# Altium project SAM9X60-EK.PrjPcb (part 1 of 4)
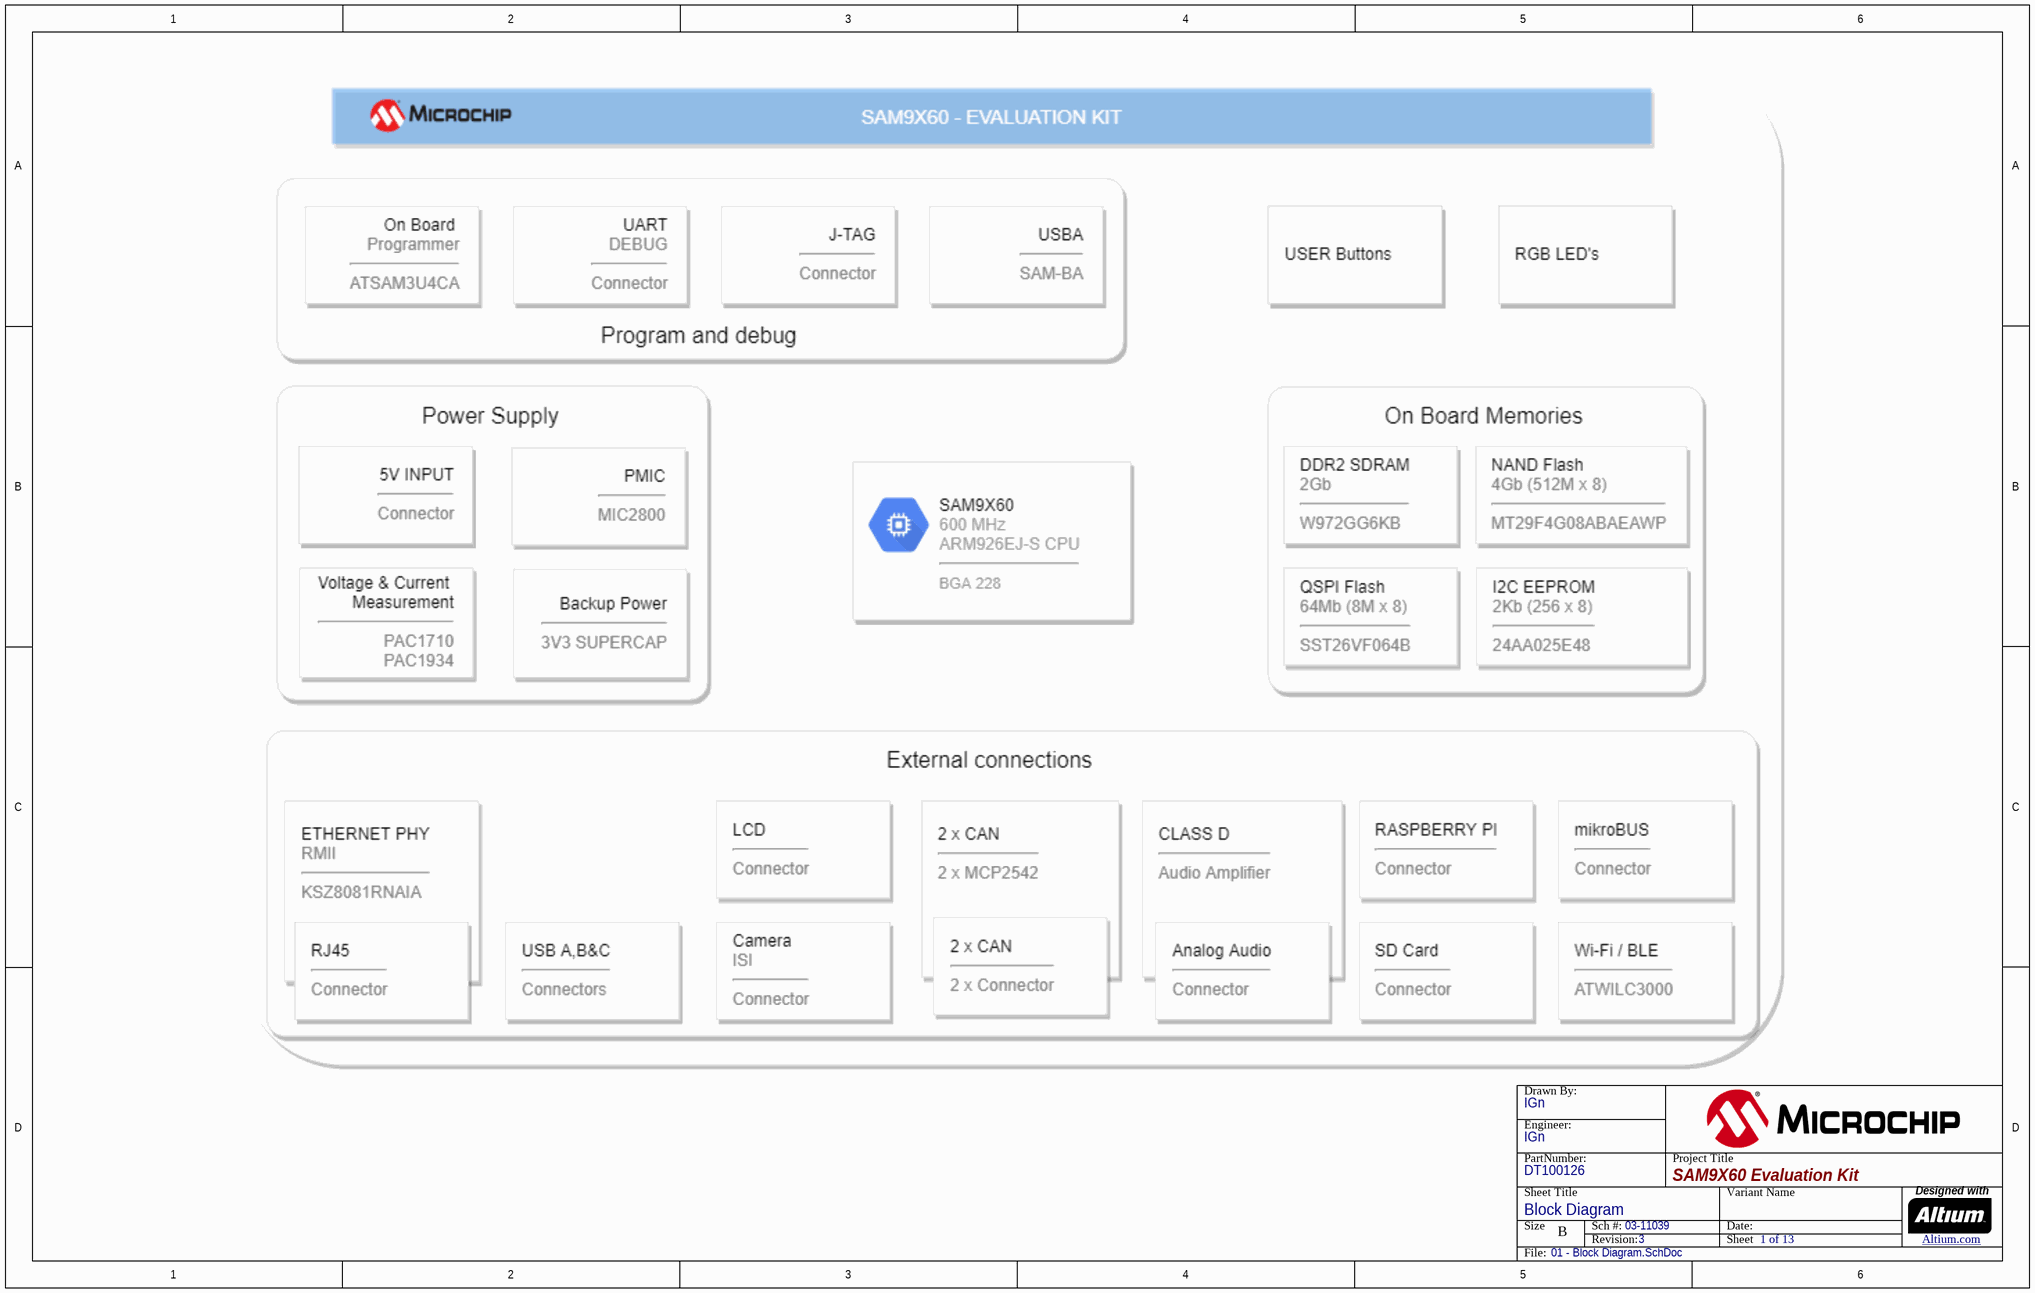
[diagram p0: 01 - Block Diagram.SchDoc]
ProjectBoardNumber: 11039; ProjectDrawnBy: IGn; ProjectEngineer: IGn; ProjectName: SAM9X60-EK; ProjectPartNumber: DT100126; ProjectRevisionART: 3; ProjectRevisionASSY: 3; ProjectRevisionFAB: 3; ProjectRevisionSCH: 3; ProjectTitle: SAM9X60 Evaluation Kit
13 sheets, 588 parts. Net scope: global (net labels, ports and power ports of the same name join across sheets).
Board file: SAM9X60-EK.PcbDoc
Sheets:
  01 - Block Diagram.SchDoc
  02 - Power supply.SchDoc
  03 - Processor SAM9X60.SchDoc
  04 - Processor IOs.SchDoc
  05 - Processor IO Expansions.SchDoc
  06 - On Board Memories.SchDoc
  07 - USB ports.SchDoc
  08 - Ethernet MAC.SchDoc
  09 - Wi-Fi BT module.SchDoc
  10 - SDMMC, CAN & CLASSD.SchDoc
  11 - Expansion connectors.SchDoc
  12 - User Interaction.SchDoc
  13 - On Board JLINK.SchDoc

## Sheet 01 - Block Diagram.SchDoc
size B; CompanyName: Microchip Technology Inc.; Organization: Microchip Technology; Address1: 2355 West Chandler Blvd.; Address2: Chandler, AZ  85224; Address4: USA; DocumentNumber: 1; SheetNumber: 1; SheetTotal: 13; SheetTitle: Block Diagram

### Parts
(Parts that share a designator on the sheet are numbered #1, #2 ... from top to bottom, then left to right.)
?#1  (no value)  (graphical)

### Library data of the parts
?#1 = Title Block B

## Sheet 02 - Power supply.SchDoc
size B; CompanyName: Microchip Technology Inc.; Organization: Microchip Technology; Address1: 2355 West Chandler Blvd.; Address2: Chandler, AZ  85224; Address4: USA; DocumentNumber: 2; SheetNumber: 2; SheetTotal: 13; SheetTitle: Power supply
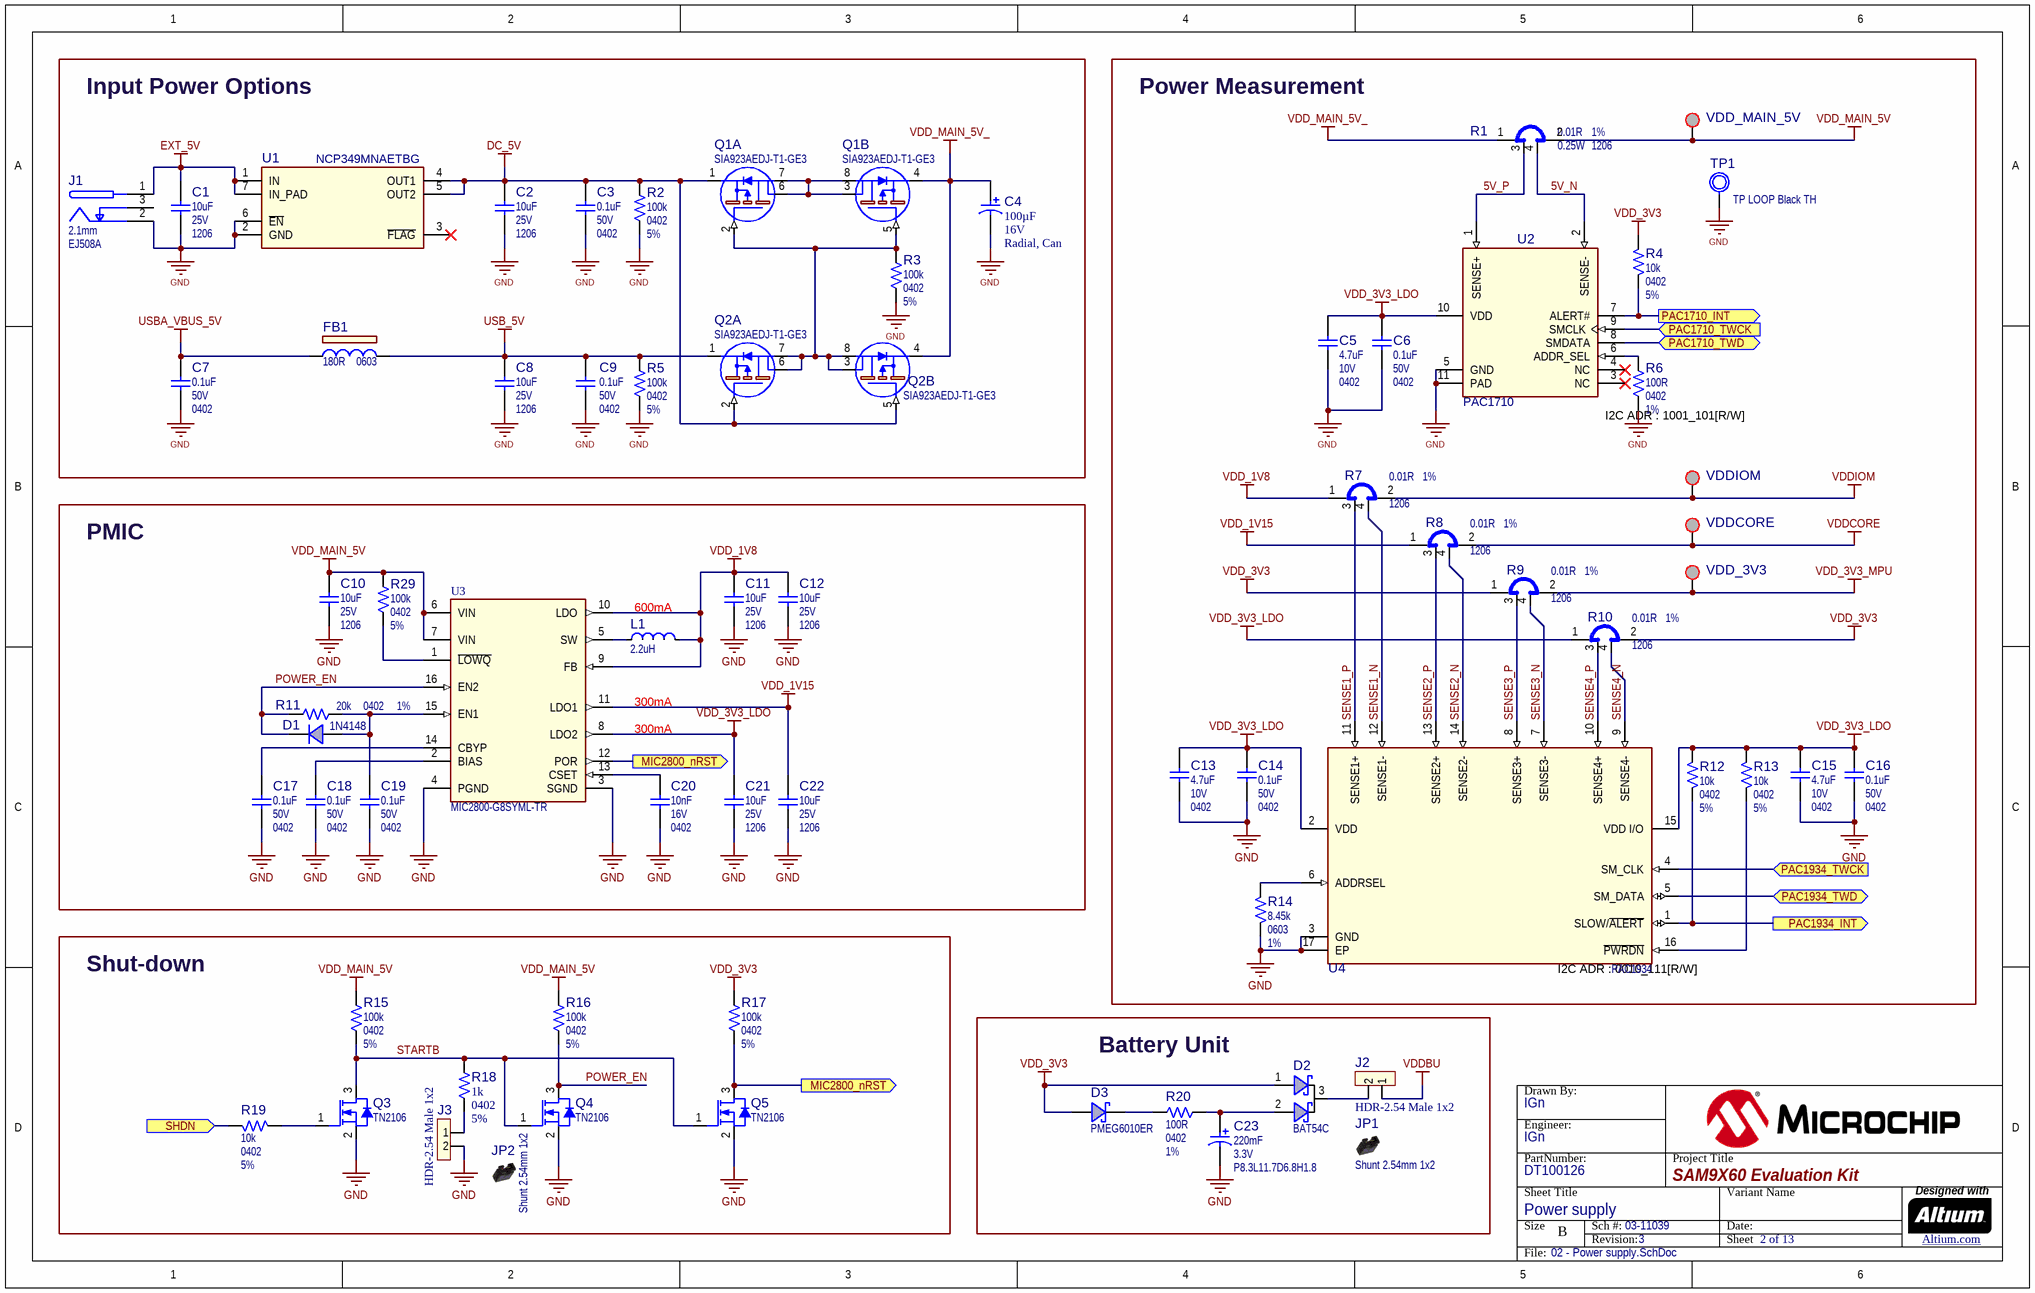
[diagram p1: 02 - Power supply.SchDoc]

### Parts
(Parts that share a designator on the sheet are numbered #1, #2 ... from top to bottom, then left to right.)
?#2  (no value)  (graphical)
C1  value 10uF  Voltage: 25V  Package: 1206  [CAP_C_1206]  (hidden comment: Capacitor NP)
C2  value 10uF  Voltage: 25V  Package: 1206  [CAP_C_1206]  (hidden comment: Capacitor NP)
C3  value 0.1uF  Voltage: 50V  Package: 0402  [CAP_C_0402]  (hidden comment: Capacitor NP)
C4  value 100µF  Voltage: 16V  Package: Radial, Can  [CAP_RAD_P2D5H12.5]  (hidden comment: Capacitor POL)
C5  value 4.7uF  Voltage: 10V  Package: 0402  [CAP_C_0402]  (hidden comment: Capacitor NP)
C6  value 0.1uF  Voltage: 50V  Package: 0402  [CAP_C_0402]  (hidden comment: Capacitor NP)
C7  value 0.1uF  Voltage: 50V  Package: 0402  [CAP_C_0402]  (hidden comment: Capacitor NP)
C8  value 10uF  Voltage: 25V  Package: 1206  [CAP_C_1206]  (hidden comment: Capacitor NP)
C9  value 0.1uF  Voltage: 50V  Package: 0402  [CAP_C_0402]  (hidden comment: Capacitor NP)
C10  value 10uF  Voltage: 25V  Package: 1206  [CAP_C_1206]  (hidden comment: Capacitor NP)
C11  value 10uF  Voltage: 25V  Package: 1206  [CAP_C_1206]  (hidden comment: Capacitor NP)
C12  value 10uF  Voltage: 25V  Package: 1206  [CAP_C_1206]  (hidden comment: Capacitor NP)
C13  value 4.7uF  Voltage: 10V  Package: 0402  [CAP_C_0402]  (hidden comment: Capacitor NP)
C14  value 0.1uF  Voltage: 50V  Package: 0402  [CAP_C_0402]  (hidden comment: Capacitor NP)
C15  value 4.7uF  Voltage: 10V  Package: 0402  [CAP_C_0402]  (hidden comment: Capacitor NP)
C16  value 0.1uF  Voltage: 50V  Package: 0402  [CAP_C_0402]  (hidden comment: Capacitor NP)
C17  value 0.1uF  Voltage: 50V  Package: 0402  [CAP_C_0402]  (hidden comment: Capacitor NP)
C18  value 0.1uF  Voltage: 50V  Package: 0402  [CAP_C_0402]  (hidden comment: Capacitor NP)
C19  value 0.1uF  Voltage: 50V  Package: 0402  [CAP_C_0402]  (hidden comment: Capacitor NP)
C20  value 10nF  Voltage: 16V  Package: 0402  [CAP_C_0402]  (hidden comment: Capacitor NP)
C21  value 10uF  Voltage: 25V  Package: 1206  [CAP_C_1206]  (hidden comment: Capacitor NP)
C22  value 10uF  Voltage: 25V  Package: 1206  [CAP_C_1206]  (hidden comment: Capacitor NP)
C23  value 220mF  Voltage: 3.3V  Package: P8.3L11.7D6.8H1.8  [CAP_AX_P8.3L11.7D6.8H1.8]  (hidden comment: Capacitor POL)
D1  value 1N4148  [SOD-323]  (hidden comment: Diode Single)
D2  value BAT54C  [SOT-23-3]  (hidden comment: Diode Schottky Dual CK)
D3  value PMEG6010ER  [SOD-123]  (hidden comment: Diode Schottky)
FB1  value 180R  Package: 0603  [IND_C_0603]  (hidden comment: Ferrite Bead)
J1  value 2.1mm  Manufacturer Part Number 1: EJ508A  [CON_JACK_POWER_TH_RA_MPD_EJ508A]  (hidden comment: CON JACK 2C 3P SPST)
J2  value HDR-2.54 Male 1x2  [HDR_M_2.54_1x2]  (hidden comment: Header 1x2)
J3  value HDR-2.54 Male 1x2  [HDR_M_2.54_1x2]  (hidden comment: Header 1x2)
JP1  value Shunt 2.54mm 1x2  [Jumper_Mechanical]  (hidden comment: Jumper Mechanical)  (mechanical)
JP2  value Shunt 2.54mm 1x2  [Jumper_Mechanical]  (hidden comment: Jumper Mechanical)  (mechanical)
L1  value 2.2uH  [IND_C_1008]  (hidden comment: Inductor)
Q1  SIA923AEDJ-T1-GE3  [SiA923AEDJ PPAK_SC70_6L]  (parts A,B of 2)
Q2  SIA923AEDJ-T1-GE3  [SiA923AEDJ PPAK_SC70_6L]  (parts A,B of 2)
Q3  value TN2106  [SOT-23-3]  (hidden comment: Transistor MOS-N GSD)
Q4  value TN2106  [SOT-23-3]  (hidden comment: Transistor MOS-N GSD)
Q5  value TN2106  [SOT-23-3]  (hidden comment: Transistor MOS-N GSD)
R1  value 0.01R  Package: 1206  Tolerance: 1%  Power: 0.25W  [RES_C_1206_SHUNT]  (hidden comment: Shunt 4 Pin)
R2  value 100k  Package: 0402  Tolerance: 5%  [RES_C_0402]  (hidden comment: Resistor)
R3  value 100k  Package: 0402  Tolerance: 5%  [RES_C_0402]  (hidden comment: Resistor)
R4  value 10k  Package: 0402  Tolerance: 5%  [RES_C_0402]  (hidden comment: Resistor)
R5  value 100k  Package: 0402  Tolerance: 5%  [RES_C_0402]  (hidden comment: Resistor)
R6  value 100R  Package: 0402  Tolerance: 1%  [RES_C_0402]  (hidden comment: Resistor)
R7  value 0.01R  Package: 1206  Tolerance: 1%  [RES_C_1206_SHUNT]  (hidden comment: Shunt 4 Pin)
R8  value 0.01R  Package: 1206  Tolerance: 1%  [RES_C_1206_SHUNT]  (hidden comment: Shunt 4 Pin)
R9  value 0.01R  Package: 1206  Tolerance: 1%  [RES_C_1206_SHUNT]  (hidden comment: Shunt 4 Pin)
R10  value 0.01R  Package: 1206  Tolerance: 1%  [RES_C_1206_SHUNT]  (hidden comment: Shunt 4 Pin)
R11  value 20k  Package: 0402  Tolerance: 1%  [RES_C_0402]  (hidden comment: Resistor)
R12  value 10k  Package: 0402  Tolerance: 5%  [RES_C_0402]  (hidden comment: Resistor)
R13  value 10k  Package: 0402  Tolerance: 5%  [RES_C_0402]  (hidden comment: Resistor)
R14  value 8.45k  Package: 0603  Tolerance: 1%  [RES_C_0603]  (hidden comment: Resistor)
R15  value 100k  Package: 0402  Tolerance: 5%  [RES_C_0402]  (hidden comment: Resistor)
R16  value 100k  Package: 0402  Tolerance: 5%  [RES_C_0402]  (hidden comment: Resistor)
R17  value 100k  Package: 0402  Tolerance: 5%  [RES_C_0402]  (hidden comment: Resistor)
R18  value 1k  Package: 0402  Tolerance: 5%  [RES_C_0402]  (hidden comment: Resistor)
R19  value 10k  Package: 0402  Tolerance: 5%  [RES_C_0402]  (hidden comment: Resistor)
R20  value 100R  Package: 0402  Tolerance: 1%  [RES_C_0402]  (hidden comment: Resistor)
R29  value 100k  Package: 0402  Tolerance: 5%  [RES_C_0402]  (hidden comment: Resistor)
TP1  value TP LOOP Black TH  [CON_TP_TH_V_BLK_KEC_5011]  (hidden comment: GND)
U1  value NCP349MNAETBG  [DFN-6_2x1.6_EP0.4x0.35]  (hidden comment: NCP349 DFN-6)
U2  value PAC1710  [DFN-10_3x3]  (hidden comment: PAC1710 DFN-10)
U3  value MIC2800-G8SYML-TR  [QFN-16_3X3]  (hidden comment: MIC2800 VFQFN-16)
U4  value PAC1934  [UQFN-16_4X4_EP2.6X2.6]  (hidden comment: PAC1934 UQFN-16)
VDD_3V3  SMD Test Point  [TP_1x1_SMD]  (value not drawn)  (no BOM)
VDD_MAIN_5V  SMD Test Point  [TP_1x1_SMD]  (value not drawn)  (no BOM)
VDDCORE  SMD Test Point  [TP_1x1_SMD]  (value not drawn)  (no BOM)
VDDIOM  SMD Test Point  [TP_1x1_SMD]  (value not drawn)  (no BOM)

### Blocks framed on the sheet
Input Power Options: C1-C4 C7-C9 FB1 J1 Q1 Q2 R2 R3 R5 U1
Power Measurement: C5 C6 C13-C16 R1 R4 R6-R10 R12-R14 TP1 U2 U4 VDD_3V3 VDD_MAIN_5V VDDCORE VDDIOM
PMIC: C10-C12 C17-C22 D1 L1 R11 R29 U3
Shut-down: J3 JP2 Q3-Q5 R15-R19
Battery Unit: C23 D2 D3 J2 JP1 R20

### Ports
MIC2800_nRST (out), PAC1710_INT (out), PAC1710_TWCK (in), PAC1710_TWD (bidir), PAC1934_INT (out), PAC1934_TWCK (in), PAC1934_TWD (bidir), SHDN (in)

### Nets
DC_5V: C2.1 C3.1 Q1.1(S1) Q2.2(G1) Q2.5(G2) R2.2 U1.4(OUT1) U1.5(OUT2)
EXT_5V: C1.1 J1.1(PLUS) U1.1(IN) U1.7(IN_PAD)
GND: C1.2 C2.2 C3.2 C4.2 C5.1 C6.1 C7.2 C8.2 C9.2 C10.2 C11.2 C12.2 C13.1 C14.1 C15.1 C16.1 C17.2 C18.2 C19.2 C20.2 C21.2 C22.2 C23.2 J1.2(COM) J3.2 Q3.2(S) Q4.2(S) Q5.2(S) R2.1 R3.1 R5.1 R6.2 R14.1 TP1.1 U1.2(GND) U1.6(~{EN}) U2.5(GND) U2.11(PAD) U3.3(SGND) U3.4(PGND) U4.3(GND) U4.17(EP)
USB_5V: C8.1 C9.1 FB1.2 Q2.1(S1) R5.2
USBA_VBUS_5V: C7.1 FB1.1
VDD_1V8: C11.1 C12.1 L1.2(F) R7.1 U3.9(FB) U3.10(LDO)
VDD_1V15: C22.1 R8.1 U3.11(LDO1)
VDD_3V3: D2.1(A) D3.1(A) R4.2 R9.1 R10.2 R17.2
VDD_3V3_LDO: C5.2 C6.2 C13.2 C14.2 C15.2 C16.2 C21.1 R10.1 R12.2 R13.2 U2.10(VDD) U3.8(LDO2) U4.2(VDD) U4.15(VDD_I/O)
VDD_3V3_MPU: R9.2 VDD_3V3.1
VDD_MAIN_5V: C10.1 R1.2 R15.2 R16.2 R29.2 U3.6(VIN) U3.7(VIN) VDD_MAIN_5V.1
VDD_MAIN_5V_: C4.1 Q1.4(S2) Q2.4(S2) R1.1
VDDBU: J2.1
VDDCORE: R8.2 VDDCORE.1
VDDIOM: R7.2 VDDIOM.1
5V_N: R1.4 U2.2(SENSE-)
5V_P: R1.3 U2.1(SENSE+)
MIC2800_nRST: Q5.3(D) R17.1 U3.12(POR) ; port MIC2800_nRST
PAC1710_INT: R4.1 U2.7(ALERT#) ; port PAC1710_INT
PAC1710_TWCK: U2.9(SMCLK) ; port PAC1710_TWCK
PAC1710_TWD: U2.8(SMDATA) ; port PAC1710_TWD
PAC1934_INT: R12.1 U4.1(SLOW/~{ALERT}) ; port PAC1934_INT
PAC1934_TWCK: U4.4(SM_CLK) ; port PAC1934_TWCK
PAC1934_TWD: U4.5(SM_DATA) ; port PAC1934_TWD
POWER_EN: D1.2(K) Q4.3(D) R11.1 R16.1 U3.16(EN2)
SENSE1_N: R7.4 U4.12(SENSE1-)
SENSE1_P: R7.3 U4.11(SENSE1+)
SENSE2_N: R8.4 U4.14(SENSE2-)
SENSE2_P: R8.3 U4.13(SENSE2+)
SENSE3_N: R9.4 U4.7(SENSE3-)
SENSE3_P: R9.3 U4.8(SENSE3+)
SENSE4_N: R10.4 U4.9(SENSE4-)
SENSE4_P: R10.3 U4.10(SENSE4+)
SHDN: R19.2 ; port SHDN
STARTB: Q3.3(D) Q4.1(G) Q5.1(G) R15.1 R18.2
NetC17_1: C17.1 U3.14(CBYP)
NetC18_1: C18.1 U3.2(BIAS)
NetC19_1: C19.1 D1.1(A) R11.2 U3.15(EN1)
NetC20_1: C20.1 U3.13(CSET)
NetC23_1: C23.1 D2.2(A) R20.2
NetD2_3: D2.3(KK) J2.2
NetD3_2: D3.2(K) R20.1
NetJ3_1: J3.1 R18.1
NetL1_1: L1.1(S) U3.5(SW)
NetQ1_2: Q1.2(G1) Q1.5(G2) Q2.3(D2) Q2.6(D1) Q2.7(D1_2) Q2.8(D2_2) R3.2
NetQ1_3: Q1.3(D2) Q1.6(D1) Q1.7(D1_2) Q1.8(D2_2)
NetQ3_1: Q3.1(G) R19.1
NetR6_1: R6.1 U2.6(ADDR_SEL)
NetR13_1: R13.1 U4.16(~{PWRDN})
NetR14_2: R14.2 U4.6(ADDRSEL)
NetR29_1: R29.1 U3.1(~{LOWQ})

Not connected (* = marked no-connect by the designer): J1 3(SWITCH); U1 3(~{FLAG})*; U2 3(NC)* 4(NC)*

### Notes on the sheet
- I2C ADR : 1001_101[R/W]
- (near L1) 600mA
- 300mA
- (near U4) I2C ADR : 0010_111[R/W]

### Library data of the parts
?#2 = Title Block B
C1 C2 C8 C10-C12 C21 C22 = CAP1418: Capacitor; Manufacturer 1: Samsung Electro-Mechanics America, Inc; Manufacturer Part Number 1: CL31B106KAHNFNE; Description_: CAP CER 10uF 25V 10% X7R SMD 1206; Dev Tools Status: Design; Tolerance: 10%; Temperature Coeffcient: X7R; Type: Ceramic; Populated: YES; Owner: Sorin Stanoaia
C3 C6 C7 C9 C14 C16-C19 = CAP1463: Capacitor; Manufacturer 1: TDK Corporation; Manufacturer Part Number 1: C1005X7R1H104K050BB; Description_: CAP CER 0.1uF 50V 10% X7R SMD 0402; Dev Tools Status: Production; Tolerance: 10%; Temperature Coeffcient: X7R; Type: Ceramic; Owner: Jamus Griego; Populated: YES
C4 = CAP1834: Capacitor; Manufacturer 1: Wurth Electronics Inc.; Manufacturer Part Number 1: 860010372006; Description_: CAP 100 UF 20% 16 V; Dev Tools Status: Design; Tolerance: ±20%; Type: Aluminum; Owner: Ed Kennedy; Populated: YES
C5 C13 C15 = CAP1684: Capacitor; Manufacturer 1: TDK Corporation; Manufacturer Part Number 1: C1005X5R1A475K050BC; Description_: CAP CER 4.7uF 10V 10% X5R SMD 0402; Dev Tools Status: Production; Tolerance: 10%; Temperature Coeffcient: X5R; Type: Ceramic; Owner: Jesus Aviles; Populated: YES
C20 = CAP0278: Capacitor; Manufacturer 1: KEMET; Manufacturer Part Number 1: C0402C103K4RACTU; Description_: CAP CER 10000pF 16V 10% X7R SMD 0402; Dev Tools Status: Production; Tolerance: 10%; Temperature Coeffcient: X7R; Type: Ceramic; Populated: YES
C23 = CAP1762: Capacitor; Manufacturer 1: Elna America; Manufacturer Part Number 1: DSK-3R3H204T614-H2L; Description_: CAP SUPERCAP 200mF 3.3V -20% +80% 200Ohm AX P8.3L11.7D6.8H1.8; Dev Tools Status: Production; Tolerance: -20%, +80%; ESR: 200R; Type: Supercap; Owner: Alexandru Chiser - M19201; Populated: YES
D1 = DIODE0096: Manufacturer 1: Diodes Incorporated; Manufacturer Part Number 1: 1N4148WS-7-F; Description_: DIO RECT 1N4148WS 1.25V 150mA 75V SOD-323; Dev Tools Status: Production; Type: Rectifier Single; Forward Current: 150mA; Power: 200mW; Reverse Current: 50uA; Reverse Voltage: 75V; Populated: YES
D2 = DIODE0056: Manufacturer 1: Diodes Incorporated; Manufacturer Part Number 1: BAT54CTA; Description_: DIO SCTKYARR BAT54C 530mV 200mA 30V SOT-23-3; Dev Tools Status: Production; Type: Schottky Array; Forward Current: 200mA; Power: 330mW; Reverse Current: 2.5uA; Reverse Voltage: 30V; Populated: Yes
D3 = DIODE1254: DIO SCTKY RB160M-60TR 550mV 1A 60V SMD SOD-123F; Manufacturer 1: NXP Semiconductors                                                                               NXP Semiconductors; Manufacturer Part Number 1: PMEG6010ER,115; Description_: DIODE SCTKY PMEG6010ER 530mV 1A 60V SMD SOD-123; Dev Tools Status: Design; Type: Schottky Single; Power: 0.95W; Reverse Current: 60uA; Reverse Recovery Time: 500ns; Owner: Sorin Stanoaia; Populated: YES
FB1 = IND1453: Manufacturer 1: Murata Electronics North America; Manufacturer Part Number 1: BLM18PG181SN1D; Description_: FERRITE 180R 1.5A SMD 0603; Dev Tools Status: Design; Owner: Dragos Danaila; DCR: 0.09R; Saturation Current: 1.5A; Test Frequency: 100MHz; Populated: YES
J1 = CON1560: Manufacturer 1: MPD (Memory Protection Devices); Description_: CON POWER 2.1mm 5.5mm Switch Slotted TH R/A; Dev Tools Status: Production; Owner: Mark Loper; Populated: YES
J2 J3 = CON1312: Manufacturer 1: Sullins Connector Solutions; Manufacturer Part Number 1: PREC002SAAN-RC; Description_: CON HDR-2.54 Male 1x2 Tin 5.84MH TH VERT; Dev Tools Status: Production; Owner: Randolph Sobrepena; Populated: YES
JP1 JP2 = HW1006: Manufacturer 1: 3M; Manufacturer Part Number 1: 969102-0000-DA; MCHP-ID: HW1006; Description_: MECH HW JUMPER 2.54mm 1x2; Dev Tools Status: Production; Owner: Mike Ragsdale; Populated: MECH
L1 = IND1348: Manufacturer 1: TDK; Manufacturer Part Number 1: MLP2520H2R2MT0S1; Description_: INDUCTOR 2.2uH 1.3A 20% SMD 1008; Dev Tools Status: Design; Owner: Razvan Cristescu; DCR: 0.117R; RMS Current: 1.3A; Test Frequency: 2MHz; Populated: YES
Q1 Q2 = TRA1245: Manufacturer 1: Vishay Siliconix; Description_: TRANS FET DUAL P+P SIA923AEDJ -20V -4.5A 7.8W SC70-6L; Dev Tools Status: Design; Type: FET; Current: -4.5A; Drain to Source Voltage: -20V; Gate to Source Voltage: 900mV; Power: 7.8W; Owner: Dragos Danaila; Populated: YES
Q3-Q5 = MIC7420: Transistor MOS; Manufacturer 1: Microchip Technology; Manufacturer Part Number 1: TN2106K1-G; Description_: MCHP ANALOG MOSFET N-CH TN2106 60V 280mA 360mW 2.5R SOT23-3; Type: MOSFET; Dev Tools Status: Production; Owner: Ilie Galan; Populated: YES
R1 = RSMT1231: Shunt; Manufacturer 1: Yageo; Manufacturer Part Number 1: PF1206FRF070R01L; Description_: RES SHUNT 0.01R 1% 1/4W 1206; Dev Tools Status: Design; Voltage: 50mV; Temperature Coeffcient: 100ppm/C; Current: 5A; Owner: Dragos Danaila; Populated: YES
R2 R3 R5 R15-R17 R29 = RES2196: Manufacturer 1: Yageo; Manufacturer Part Number 1: RC0402JR-07100KL; Description_: RES TKF 100k 5% 1/16W SMD 0402; Dev Tools Status: Design; Temperature Coeffcient: 100ppm/C; Power: 1/16W; Owner: Ilie Galan; Populated: YES
R4 R12 R13 R19 = RSMT0439: Manufacturer 1: Vishay; Manufacturer Part Number 1: CRCW040210K0JNED; Description_: RES TKF 10k 5% 1/16W SMD 0402; Dev Tools Status: Production; Voltage: 50V; Temperature Coeffcient: 100ppm/C; Power: 1/16W; Populated: Yes
R6 R20 = RES1587: Manufacturer 1: Yageo; Manufacturer Part Number 1: RC0402FR-07100RL; Description_: RES TKF 100R 1% 1/16W SMD 0402; Dev Tools Status: Design; Voltage: 50V; Temperature Coeffcient: 100ppm/C; Power: 1/16W; Owner: Sorin Stanoaia; Populated: YES
R7-R10 = RSMT1231: Shunt; Manufacturer 1: Yageo; Manufacturer Part Number 1: PF1206FRF070R01L; Description_: RES SHUNT 0.01R 1% 1/4W 1206; Dev Tools Status: Design; Voltage: 50mV; Temperature Coeffcient: 100ppm/C; Current: 5A; Power: 1/4W; Owner: Dragos Danaila; Populated: YES
R11 = RSMT1238: Manufacturer 1: Yageo; Manufacturer Part Number 1: RC0402FR-0720KL; Description_: RES TKF 20K 1% 1/16W SMD 0402; Dev Tools Status: Design; Voltage: 100V; Temperature Coeffcient: 100ppm/C; Current: 1A; Power: 1/16; Owner: Dragos Danaila; Populated: YES
R14 = RSMT0440: Manufacturer 1: Yageo; Manufacturer Part Number 1: 9C06031A8451FKHFT; Description_: RES TKF 8.45k 1% 1/10W SMD 0603; Dev Tools Status: Production; Voltage: 50V; Temperature Coeffcient: 100ppm/C; Power: 1/10W; Populated: Yes
R18 = RSMT0316: Manufacturer 1: Panasonic; Manufacturer Part Number 1: ERJ-2GEJ102X; Description_: RES TKF 1k 5% 1/16W SMD 0402; Dev Tools Status: Production; Voltage: 50V; Temperature Coeffcient: 200ppm/C; Power: 1/16W; Owner: Tad Ahlvers; Populated: YES
TP1 = MISC0025: Test Point; Manufacturer 1: Keystone; Manufacturer Part Number 1: 5011; Description_: CON TP LOOP Black TH; Dev Tools Status: Production; Owner: Tad Ahlvers; Populated: YES
U1 = IC1481: Manufacturer 1: ON Semiconductor; MCHP-ID: IC1481; Description_: IC POWER NCP349MNAETBG Power Supply Controller Overvoltage Protection DFN-6; Dev Tools Status: Design; Vin: 1.2 V to 28 V; Owner: Ciprian Abramov; Populated: YES
U2 = MIC6142: Manufacturer 1: Microchip Technology; Manufacturer Part Number 1: PAC1710-1-AIA-TR; Description_: MCHP ANALOG CURRENT SENSE MONITOR PAC1710-1-AIA-TR DFN-10; Dev Tools Status: Production; Owner: Bogdan Popescu; Populated: YES
U3 = MIC7858: Manufacturer 1: Microchip Technology; Manufacturer Part Number 1: MIC2800-G8SYML; Description_: MCHP ANALOG SWITCHER Buck 1.8V to 3.3V MIC2800-G8SYML-TR VFQFN-16; Dev Tools Status: Design; Owner: Dragos Danaila; Populated: YES
U4 = MIC7010: Manufacturer 1: Microchip Technology; Manufacturer Part Number 1: PAC1934-I/JQ; Description_: MCHP ANALOG POWER CURRENT SENSE MONITOR PAC1934-I/JQ UQFN-16; Dev Tools Status: Production; Owner: Razvan Cristescu; Populated: YES
VDD_3V3 VDD_MAIN_5V VDDCORE VDDIOM = TEST-POINT: Test Point pad 1.00mm

## Sheet 03 - Processor SAM9X60.SchDoc
size B; CompanyName: Microchip Technology Inc.; Organization: Microchip Technology; Address1: 2355 West Chandler Blvd.; Address2: Chandler, AZ  85224; Address4: USA; DocumentNumber: 3; SheetNumber: 3; SheetTotal: 13; SheetTitle: Processor SAM9X60
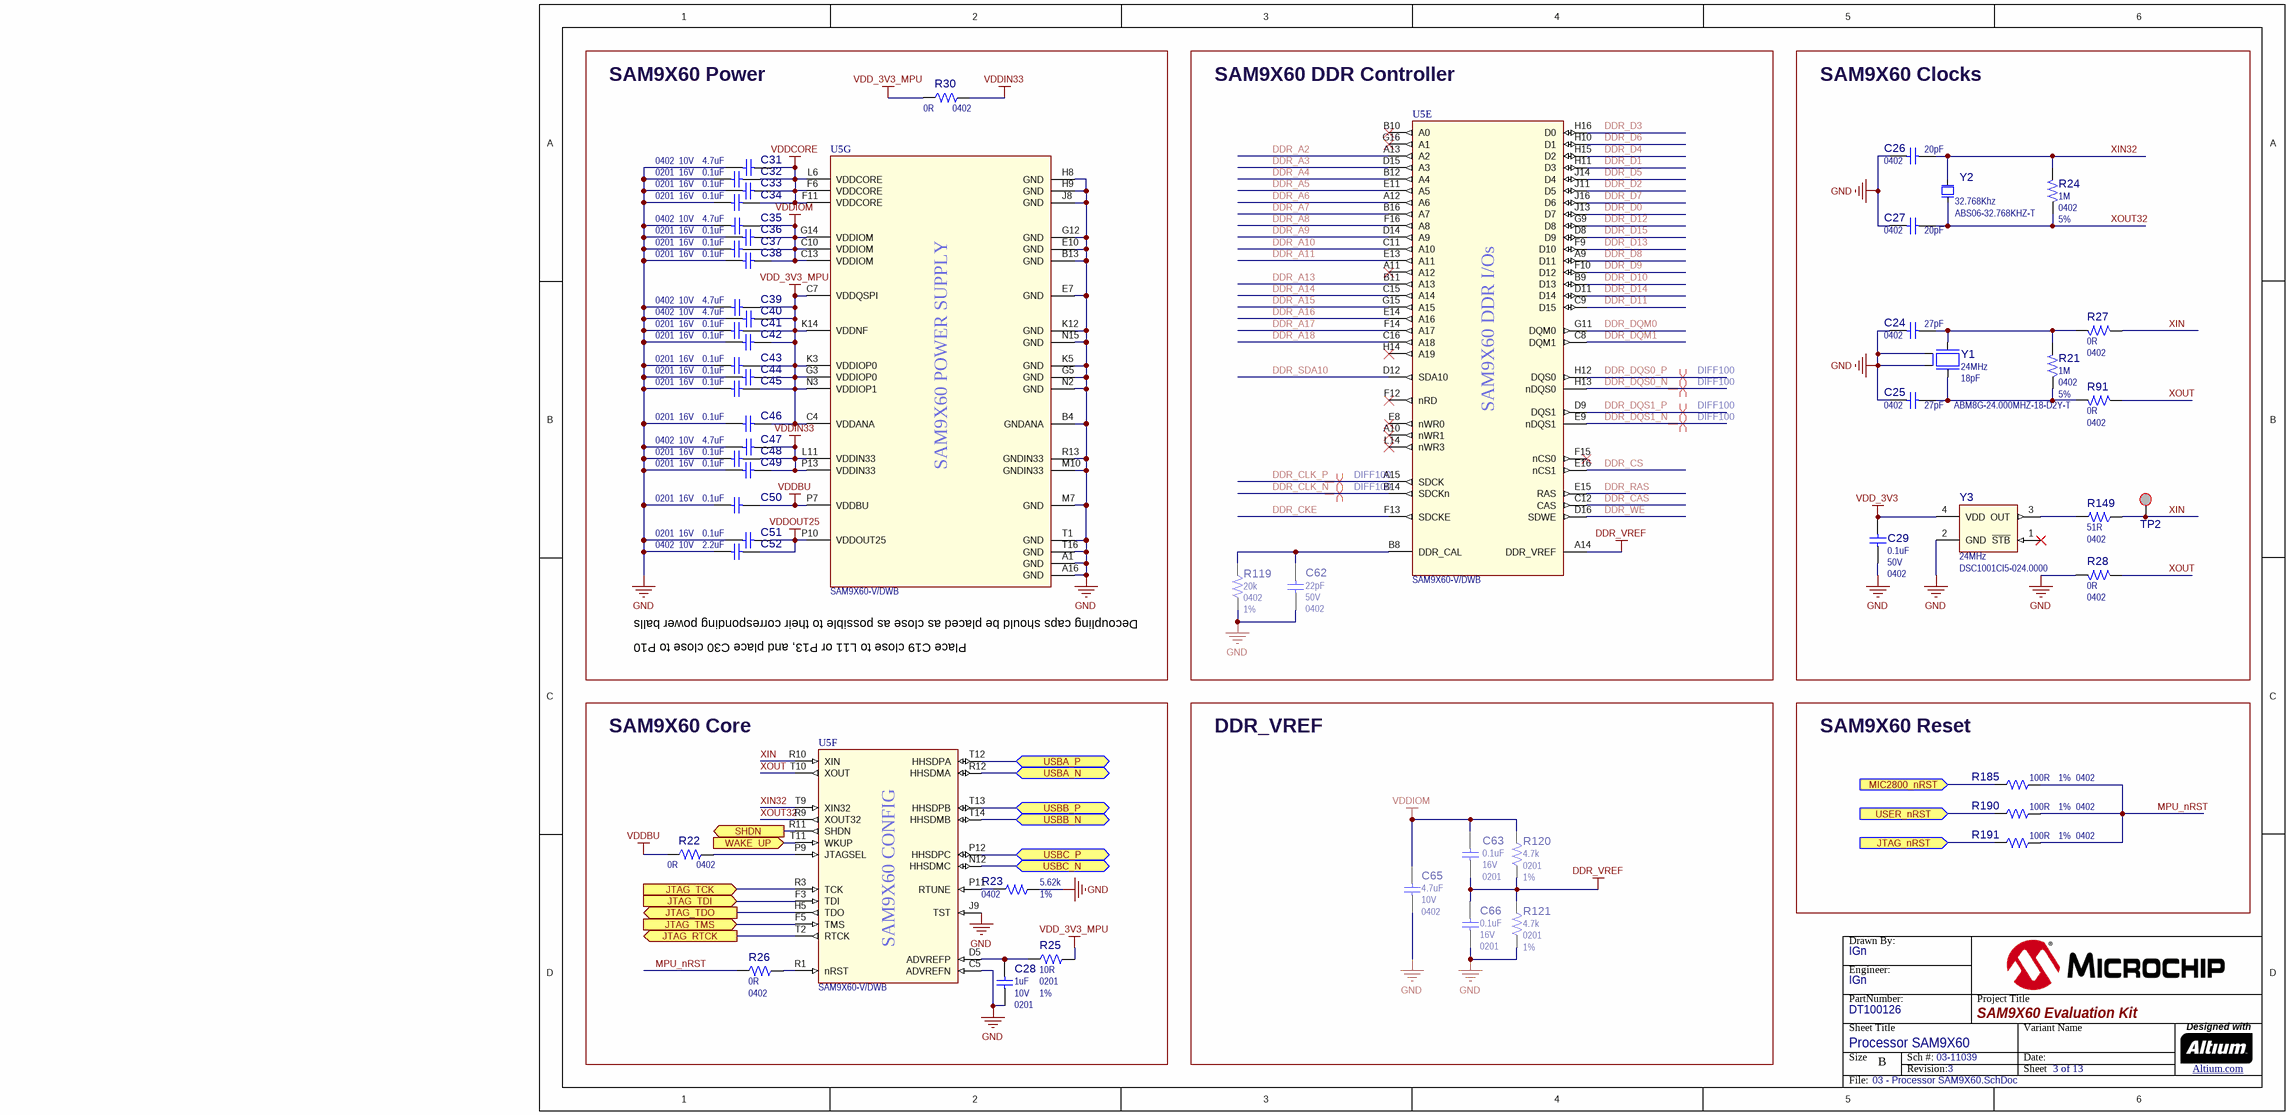
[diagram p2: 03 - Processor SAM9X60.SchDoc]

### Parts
(Parts that share a designator on the sheet are numbered #1, #2 ... from top to bottom, then left to right.)
?#3  (no value)  (graphical)
C24  value 27pF  Package: 0402  [CAP_C_0402]  (hidden comment: Capacitor NP)
C25  value 27pF  Package: 0402  [CAP_C_0402]  (hidden comment: Capacitor NP)
C26  value 20pF  Package: 0402  [CAP_C_0402]  (hidden comment: Capacitor NP)
C27  value 20pF  Package: 0402  [CAP_C_0402]  (hidden comment: Capacitor NP)
C28  value 1uF  Voltage: 10V  Package: 0201  [CAP_C_0201]  (hidden comment: Capacitor NP)
C29  value 0.1uF  Voltage: 50V  Package: 0402  [CAP_C_0402]  (hidden comment: Capacitor NP)
C31  value 4.7uF  Voltage: 10V  Package: 0402  [CAP_C_0402]  (hidden comment: Capacitor NP)
C32  value 0.1uF  Voltage: 16V  Package: 0201  [CAP_C_0201]  (hidden comment: Capacitor NP)
C33  value 0.1uF  Voltage: 16V  Package: 0201  [CAP_C_0201]  (hidden comment: Capacitor NP)
C34  value 0.1uF  Voltage: 16V  Package: 0201  [CAP_C_0201]  (hidden comment: Capacitor NP)
C35  value 4.7uF  Voltage: 10V  Package: 0402  [CAP_C_0402]  (hidden comment: Capacitor NP)
C36  value 0.1uF  Voltage: 16V  Package: 0201  [CAP_C_0201]  (hidden comment: Capacitor NP)
C37  value 0.1uF  Voltage: 16V  Package: 0201  [CAP_C_0201]  (hidden comment: Capacitor NP)
C38  value 0.1uF  Voltage: 16V  Package: 0201  [CAP_C_0201]  (hidden comment: Capacitor NP)
C39  value 4.7uF  Voltage: 10V  Package: 0402  [CAP_C_0402]  (hidden comment: Capacitor NP)
C40  value 4.7uF  Voltage: 10V  Package: 0402  [CAP_C_0402]  (hidden comment: Capacitor NP)
C41  value 0.1uF  Voltage: 16V  Package: 0201  [CAP_C_0201]  (hidden comment: Capacitor NP)
C42  value 0.1uF  Voltage: 16V  Package: 0201  [CAP_C_0201]  (hidden comment: Capacitor NP)
C43  value 0.1uF  Voltage: 16V  Package: 0201  [CAP_C_0201]  (hidden comment: Capacitor NP)
C44  value 0.1uF  Voltage: 16V  Package: 0201  [CAP_C_0201]  (hidden comment: Capacitor NP)
C45  value 0.1uF  Voltage: 16V  Package: 0201  [CAP_C_0201]  (hidden comment: Capacitor NP)
C46  value 0.1uF  Voltage: 16V  Package: 0201  [CAP_C_0201]  (hidden comment: Capacitor NP)
C47  value 4.7uF  Voltage: 10V  Package: 0402  [CAP_C_0402]  (hidden comment: Capacitor NP)
C48  value 0.1uF  Voltage: 16V  Package: 0201  [CAP_C_0201]  (hidden comment: Capacitor NP)
C49  value 0.1uF  Voltage: 16V  Package: 0201  [CAP_C_0201]  (hidden comment: Capacitor NP)
C50  value 0.1uF  Voltage: 16V  Package: 0201  [CAP_C_0201]  (hidden comment: Capacitor NP)
C51  value 0.1uF  Voltage: 16V  Package: 0201  [CAP_C_0201]  (hidden comment: Capacitor NP)
C52  value 2.2uF  Voltage: 10V  Package: 0402  [CAP_C_0402]  (hidden comment: Capacitor NP)
C62  value 22pF  Voltage: 50V  Package: 0402  [CAP_C_0402]  (hidden comment: Capacitor NP)
C63  value 0.1uF  Voltage: 16V  Package: 0201  [CAP_C_0201]  (hidden comment: Capacitor NP)
C65  value 4.7uF  Voltage: 10V  Package: 0402  [CAP_C_0402]  (hidden comment: Capacitor NP)
C66  value 0.1uF  Voltage: 16V  Package: 0201  [CAP_C_0201]  (hidden comment: Capacitor NP)
R21  value 1M  Package: 0402  Tolerance: 5%  [RES_C_0402]  (hidden comment: Resistor)
R22  value 0R  Package: 0402  [RES_C_0402]  (hidden comment: Resistor)
R23  value 5.62k  Package: 0402  Tolerance: 1%  [RES_C_0402]  (hidden comment: Resistor)
R24  value 1M  Package: 0402  Tolerance: 5%  [RES_C_0402]  (hidden comment: Resistor)
R25  value 10R  Package: 0201  Tolerance: 1%  [RES_C_0201]  (hidden comment: Resistor)
R26  value 0R  Package: 0402  [RES_C_0402]  (hidden comment: Resistor)
R27  value 0R  Package: 0402  [RES_C_0402]  (hidden comment: Resistor)
R28  value 0R  Package: 0402  [RES_C_0402]  (hidden comment: Resistor)
R30  value 0R  Package: 0402  [RES_C_0402]  (hidden comment: Resistor)
R91  value 0R  Package: 0402  [RES_C_0402]  (hidden comment: Resistor)
R119  value 20k  Package: 0402  Tolerance: 1%  [RES_C_0402]  (hidden comment: Resistor)
R120  value 4.7k  Package: 0201  Tolerance: 1%  [RES_C_0201]  (hidden comment: Resistor)
R121  value 4.7k  Package: 0201  Tolerance: 1%  [RES_C_0201]  (hidden comment: Resistor)
R149  value 51R  Package: 0402  [RES_C_0402]  (hidden comment: Resistor)
R185  value 100R  Package: 0402  Tolerance: 1%  [RES_C_0402]  (hidden comment: Resistor)
R190  value 100R  Package: 0402  Tolerance: 1%  [RES_C_0402]  (hidden comment: Resistor)
R191  value 100R  Package: 0402  Tolerance: 1%  [RES_C_0402]  (hidden comment: Resistor)
TP2  SMD Test Point  [TP_1x1_SMD]  (value not drawn)  (no BOM)
U5  value SAM9X60-V/DWB  [SAM9X60 TFBGA-228]  (hidden comment: SAM9X60 TFBGA-228)  (parts E,F,G of 7)
Y1  value 24MHz  Load Capacitance: 18pF  Manufacturer Part Number 1: ABM8G-24.000MHZ-18-D2Y-T  [CRYSTAL_ABM8G]  (hidden comment: Crystal 4 Pins)
Y2  value 32.768Khz  Manufacturer Part Number 1: ABS06-32.768KHZ-T  [CRYSTAL_ABS06]  (hidden comment: Crystal 2 Pins)
Y3  value 24MHz  Manufacturer Part Number 1: DSC1001CI5-024.0000  [CDFN-4_3.2X2.5]  (hidden comment: DSC10xx DFN-4)

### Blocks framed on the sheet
SAM9X60 Power: C31-C52 R30 U5
SAM9X60 DDR Controller: C62 R119 U5
SAM9X60 Clocks: C24-C27 C29 R21 R24 R27 R28 R91 R149 TP2 Y1-Y3
SAM9X60 Core: C28 R22 R23 R25 R26 U5
DDR_VREF: C63 C65 C66 R120 R121
SAM9X60 Reset: R185 R190 R191

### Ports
JTAG_nRST (in), JTAG_RTCK (out), JTAG_TCK (in), JTAG_TDI (in), JTAG_TDO (out), JTAG_TMS (in), MIC2800_nRST (in), SHDN (out), USBA_N (bidir), USBA_P (bidir), USBB_N (bidir), USBB_P (bidir), USBC_N (bidir), USBC_P (bidir), USER_nRST (in), WAKE_UP (in)

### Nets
DDR_VREF: C63.1 C66.2 R120.1 R121.2 U5.A14(DDR_VREF)
GND: C24.2 C25.2 C26.2 C27.2 C28.1 C29.1 C31.1 C32.2 C33.2 C34.2 C35.1 C36.2 C37.2 C38.2 C39.1 C40.1 C41.2 C42.2 C43.2 C44.2 C45.2 C46.2 C47.1 C48.2 C49.2 C50.2 C51.2 C52.2 C62.1 C65.1 C66.1 R23.1 R28.2 R119.1 R121.1 U5.A1(GND) U5.A16(GND) U5.B4(GNDANA) U5.B13(GND) U5.C5(ADVREFN) U5.E7(GND) U5.E10(GND) U5.G5(GND) U5.G12(GND) U5.H8(GND) U5.H9(GND) U5.J8(GND) U5.J9(TST) U5.K5(GND) U5.K12(GND) U5.M7(GND) U5.M10(GNDIN33) U5.N2(GND) U5.N15(GND) U5.R13(GNDIN33) U5.T1(GND) U5.T16(GND) Y1.2(GND) Y1.4(GND) Y3.2(GND)
VDD_3V3: C29.2 Y3.4(VDD)
VDD_3V3_MPU: C39.2 C40.2 C41.1 C42.1 C43.1 C44.1 C45.1 C46.1 R25.2 R30.1 U5.C4(VDDANA) U5.C7(VDDQSPI) U5.G3(VDDIOP0) U5.K3(VDDIOP0) U5.K14(VDDNF) U5.N3(VDDIOP1)
VDDBU: C50.1 R22.1 U5.P7(VDDBU)
VDDCORE: C31.2 C32.1 C33.1 C34.1 U5.F6(VDDCORE) U5.F11(VDDCORE) U5.L6(VDDCORE)
VDDIN33: C47.2 C48.1 C49.1 R30.2 U5.L11(VDDIN33) U5.P13(VDDIN33)
VDDIOM: C35.2 C36.1 C37.1 C38.1 C63.2 C65.2 R120.2 U5.C10(VDDIOM) U5.C13(VDDIOM) U5.G14(VDDIOM)
VDDOUT25: C51.1 C52.1 U5.P10(VDDOUT25)
DDR_A2: U5.A13(A2)
DDR_A3: U5.D15(A3)
DDR_A4: U5.B12(A4)
DDR_A5: U5.E11(A5)
DDR_A6: U5.A12(A6)
DDR_A7: U5.B16(A7)
DDR_A8: U5.F16(A8)
DDR_A9: U5.D14(A9)
DDR_A10: U5.C11(A10)
DDR_A11: U5.E13(A11)
DDR_A13: U5.B11(A13)
DDR_A14: U5.C15(A14)
DDR_A15: U5.G15(A15)
DDR_A16: U5.E14(A16)
DDR_A17: U5.F14(A17)
DDR_A18: U5.C16(A18)
DDR_CAS: U5.C12(CAS)
DDR_CKE: U5.F13(SDCKE)
DDR_CLK_N: U5.B14(SDCKn)
DDR_CLK_P: U5.A15(SDCK)
DDR_CS: U5.E16(nCS1)
DDR_D0: U5.J13(D7)
DDR_D1: U5.H11(D3)
DDR_D2: U5.J11(D5)
DDR_D3: U5.H16(D0)
DDR_D4: U5.H15(D2)
DDR_D5: U5.J14(D4)
DDR_D6: U5.H10(D1)
DDR_D7: U5.J16(D6)
DDR_D8: U5.A9(D11)
DDR_D9: U5.F10(D12)
DDR_D10: U5.B9(D13)
DDR_D11: U5.C9(D15)
DDR_D12: U5.G9(D8)
DDR_D13: U5.F9(D10)
DDR_D14: U5.D11(D14)
DDR_D15: U5.D8(D9)
DDR_DQM0: U5.G11(DQM0)
DDR_DQM1: U5.C8(DQM1)
DDR_DQS0_N: U5.H13(nDQS0)
DDR_DQS0_P: U5.H12(DQS0)
DDR_DQS1_N: U5.E9(nDQS1)
DDR_DQS1_P: U5.D9(DQS1)
DDR_RAS: U5.E15(RAS)
DDR_SDA10: U5.D12(SDA10)
DDR_WE: U5.D16(SDWE)
JTAG_nRST: R191.1 ; port JTAG_nRST
JTAG_RTCK: U5.T2(RTCK) ; port JTAG_RTCK
JTAG_TCK: U5.R3(TCK) ; port JTAG_TCK
JTAG_TDI: U5.F3(TDI) ; port JTAG_TDI
JTAG_TDO: U5.H5(TDO) ; port JTAG_TDO
JTAG_TMS: U5.F5(TMS) ; port JTAG_TMS
MIC2800_nRST: R185.1 ; port MIC2800_nRST
MPU_nRST: R26.1 R185.2 R190.2 R191.2
SHDN: U5.R11(SHDN) ; port SHDN
USBA_N: U5.R12(HHSDMA) ; port USBA_N
USBA_P: U5.T12(HHSDPA) ; port USBA_P
USBB_N: U5.T14(HHSDMB) ; port USBB_N
USBB_P: U5.T13(HHSDPB) ; port USBB_P
USBC_N: U5.N12(HHSDMC) ; port USBC_N
USBC_P: U5.P12(HHSDPC) ; port USBC_P
USER_nRST: R190.1 ; port USER_nRST
WAKE_UP: U5.T11(WKUP) ; port WAKE_UP
XIN: R27.1 R149.1 TP2.1 U5.R10(XIN)
XIN32: C26.1 R24.2 U5.T9(XIN32) Y2.2(Osc2)
XOUT: R28.1 R91.1 U5.T10(XOUT)
XOUT32: C27.1 R24.1 U5.R9(XOUT32) Y2.1(Osc1)
NetC24_1: C24.1 R21.2 R27.2 Y1.1(Osc1)
NetC25_1: C25.1 R21.1 R91.2 Y1.3(Osc2)
NetC28_2: C28.2 R25.1 U5.D5(ADVREFP)
NetC62_2: C62.2 R119.2 U5.B8(DDR_CAL)
NetR22_2: R22.2 U5.P9(JTAGSEL)
NetR23_2: R23.2 U5.P11(RTUNE)
NetR26_2: R26.2 U5.R1(nRST)
NetR149_2: R149.2 Y3.3(OUT)

Not connected (* = marked no-connect by the designer): U5 A10(nWR1)* A11(A12)* B10(A0)* E8(nWR0)* F12(nRD)* F15(nCS0)* G16(A1)* H14(A19)* L14(nWR3)*; Y3 1(~{STB})*

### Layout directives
differential pair; differential pair class DIFF100; net class DIFF100; rule Matched Net Lengths [Tolerance = 10mil]: DDR_CLK_N, DDR_CLK_P, DDR_DQS0_N, DDR_DQS0_P, DDR_DQS1_N, DDR_DQS1_P

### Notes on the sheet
- (near U5) SAM9X60 DDR I/Os
- (near U5) SAM9X60 POWER SUPPLY
- Decoupling caps should be placed as close as possible to their corresponding power balls
- Place C19 close to L11 or P13, and place C30 close to P10
- (near U5) SAM9X60 CONFIG

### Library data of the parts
?#3 = Title Block B
C24 C25 = CAP0349: Capacitor; Manufacturer 1: Murata; Manufacturer Part Number 1: GRM1555C1H270JA01D; Voltage: 50V; Description_: CAP CER 27pF 50V 5% NP0 SMD 0402; Dev Tools Status: Production; Tolerance: 5%; Temperature Coeffcient: NP0; Type: Ceramic; Populated: DNP
C26 C27 = CAP0364: Capacitor; Manufacturer 1: Murata; Manufacturer Part Number 1: GRM1555C1H200JZ01D; Voltage: 50V; Description_: CAP CER 20pF 50V 5% C0G SMD 0402; Dev Tools Status: Production; Tolerance: 5%; Temperature Coeffcient: C0G; Type: Ceramic; Populated: DNP
C28 = CAP2024: Capacitor; Manufacturer 1: Murata Electronics North America; Manufacturer Part Number 1: GRM033R61A105ME15D; Description_: CAP CER 1uF 10V 20% X5R SMD 0201; Dev Tools Status: Design; Tolerance: 20%; Temperature Coeffcient: X5R; Type: Ceramic; Owner: Ilie Galan; Populated: YES
C29 = CAP1463: as C3 on sheet 02 - Power supply
C31 C35 C39 C40 C47 C65 = CAP1684: as C5 on sheet 02 - Power supply
C32-C34 C36-C38 C41-C46 C48-C51 C63 C66 = CAP1203: Capacitor; Manufacturer 1: Murata; Manufacturer Part Number 1: GRM033R61C104KE84D; Description_: CAP CER 0.1uF 16V 10% X5R SMD 0201; Dev Tools Status: Production; Tolerance: 10%; Temperature Coeffcient: X5R; Type: Ceramic; Owner: Tad Ahlvers; Populated: YES
C52 = CAP1468: Capacitor; Manufacturer 1: TDK Corporation; Manufacturer Part Number 1: C1005X7S1A225K050BC; Description_: CAP CER 2.2uF 10V 10% X7S SMD 0402; Dev Tools Status: Production; Tolerance: 10%; Temperature Coeffcient: X7S; Type: Ceramic; Owner: Sorin Stanoaia; Populated: YES
C62 = CAP1042: Capacitor; Manufacturer 1: Murata; Manufacturer Part Number 1: GRM1555C1H220JZ01D; Description_: CAP CER 22pF 50V 5% NP0 SMD 0402; Dev Tools Status: Production; Tolerance: 5%; Temperature Coeffcient: NP0; Type: Ceramic; Owner: Sompoch Loboonlert; Populated: Yes
R21 R24 = RES1019: Manufacturer 1: Yageo; Manufacturer Part Number 1: RC0402JR-071ML; Description_: RES TKF 1M 5% 1/16W SMD 0402; Dev Tools Status: Production; Voltage: 50V; Temperature Coeffcient: 100ppm/C; Power: 1/16W; Owner: Tad Ahlvers; Populated: DNP
R22 R27 R91 = RSMT1040: Manufacturer 1: Yageo; Manufacturer Part Number 1: RC0402JR-070RL; Description_: RES TKF 0R 1/16W SMD 0402; Dev Tools Status: Production; Power: 1/16W; Owner: Sompoch Loboonlert; Populated: DNP
R23 = RES1505: Manufacturer 1: Vishay Dale; Manufacturer Part Number 1: CRCW04025K62FKED; Description_: RES TKF 5.62k 1% 1/16W SMD 0402; Dev Tools Status: Production; Voltage: 50V; Temperature Coeffcient: 100ppm/C; Power: 1/16W; Owner: Mike Ragsdale; Populated: YES
R25 = RES2180: Manufacturer 1: Vishay Dale; Manufacturer Part Number 1: CRCW020110R0FNED; Description_: RES TKF 10R 1% 1/20W SMD 0201; Dev Tools Status: Design; Temperature Coeffcient: 200ppm/C; Power: 1/20W; Owner: Ilie Galan; Populated: YES
R26 R28 R30 = RSMT1040: Manufacturer 1: Yageo; Manufacturer Part Number 1: RC0402JR-070RL; Description_: RES TKF 0R 1/16W SMD 0402; Dev Tools Status: Production; Power: 1/16W; Owner: Sompoch Loboonlert; Populated: Yes
R119 = RSMT1238: as R11 on sheet 02 - Power supply
R120 R121 = RES1519: Manufacturer 1: Panasonic Electronic Components; Manufacturer Part Number 1: ERJ-1GEF4701C; Description_: RES TKF 4.7k 1% 1/20W SMD 0201; Dev Tools Status: Design; Voltage: 25V; Temperature Coeffcient: 200ppm/C; Power: 1/20W; Owner: Gabor Bihari; Populated: YES
R149 = RSMT1243: Manufacturer 1: Yageo; Manufacturer Part Number 1: RC0402FR-0751RL; Tolerance: 1%; Description_: RES TKF 51R 1% 1/16W SMD 0402; Dev Tools Status: Design; Voltage: 100V; Temperature Coeffcient: 100ppm/C; Current: 1A; Power: 1/16W; Owner: Ciprian Abramov; Populated: YES
R185 R190 R191 = RES1587: as R6 on sheet 02 - Power supply
TP2 = TEST-POINT: Test Point pad 1.00mm
U5 = MIC8772: SAM9X60 MPU 600MHz ARM926EJ-S TFBGA-228; Manufacturer 1: Microchip; Description_: MCHP MCU 32-BIT 600 MHz 64kB  SAM9X60-V/DWB TFBGA228; Populated: YES; MAPS Description: ARM926 MPU, BGA, IND TEMP; Dev Tools Status: Design; Owner: Ilie Galan; MPC: STU029DWBR01; LeadContent: Pb-FREE; TempRange: Various; Stage: NREL; PackageWidth: 11x11x1.2mm; PackingMedia: TRAY; ForceMinOrderQtyMult: True; MinOrderQty: 176; LeadCount: 228; Program Memory KBytes: 0; Ram: 69584; IOPins: 112; MaxSpeed: 600; OscillatorMHz: 32kHz, 12MHz; ADC Channels: 12; USART: 13; SPI: 6; CAN: 2; USBChannels: 3; DigitalTimerQty_32bit: 8
Y1 = OSC1047: Crystal; Manufacturer 1: Abracon Corporation; Description_: CRYSTAL 24MHz 18pF SMD ABM8G; Dev Tools Status: Production; Owner: Mark Loper; Populated: DNP
Y2 = OSC1063: Crystal; Manufacturer 1: Abracon LLC; Description_: CRYSTAL 32.768kHz 12.5pF SMD ABS06; Dev Tools Status: Design; Owner: Jamus Griego; Populated: DNP
Y3 = MIC7861: Manufacturer 1: Microchip Technology; Description_: MCHP CLOCK OSCILLATOR 24MHz DSC1001CI5-024.0000 DFN-4; Dev Tools Status: Design; Owner: Ilie Galan; Populated: YES

## Sheet 04 - Processor IOs.SchDoc
size B; CompanyName: Microchip Technology Inc.; Organization: Microchip Technology; Address1: 2355 West Chandler Blvd.; Address2: Chandler, AZ  85224; Address4: USA; DocumentNumber: 4; SheetNumber: 4; SheetTotal: 13; SheetTitle: Processor IOs
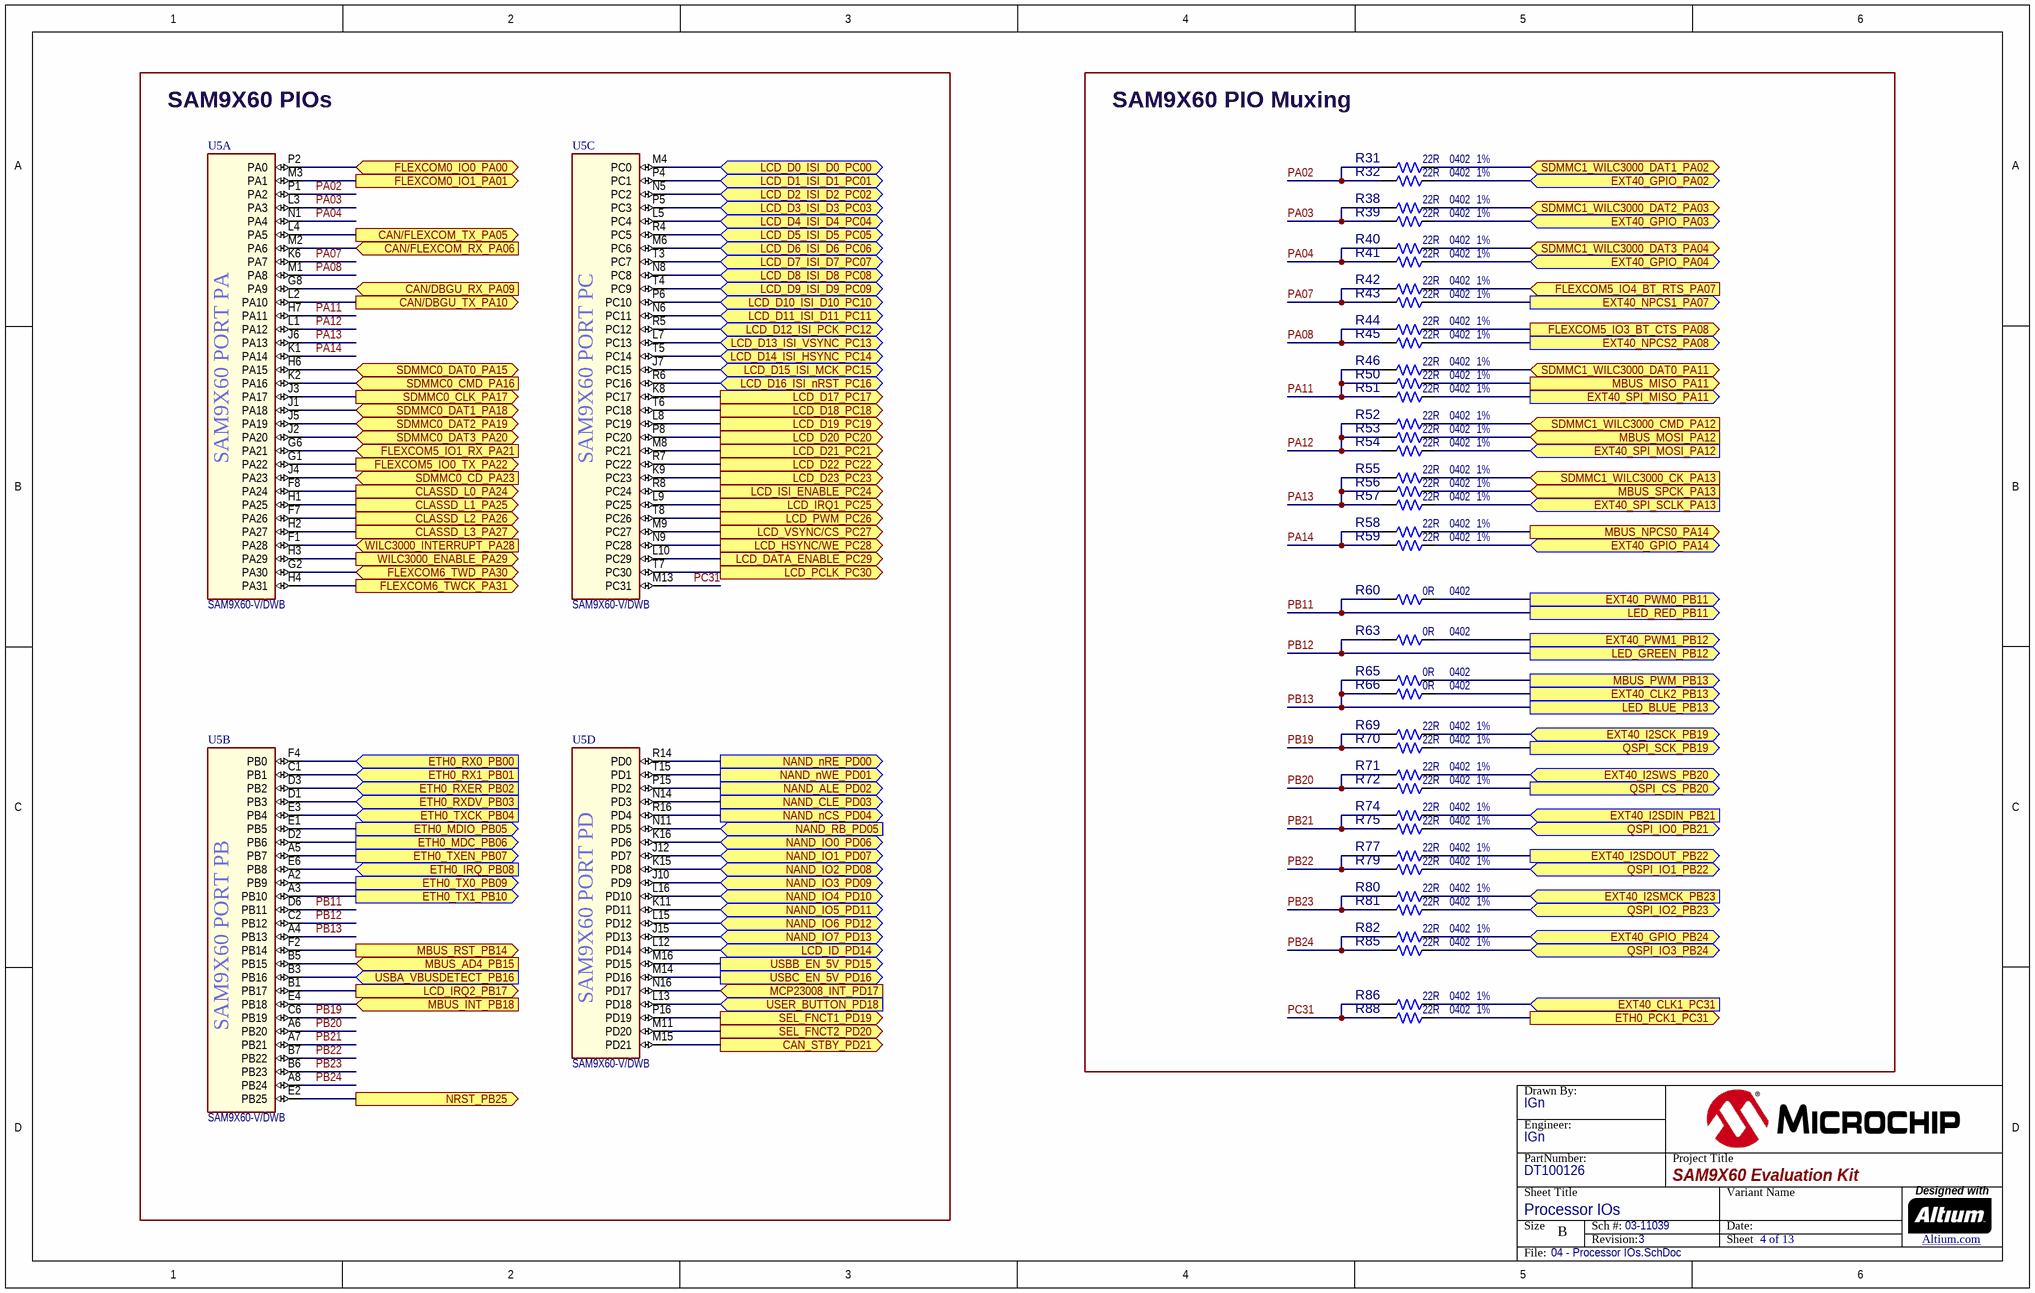
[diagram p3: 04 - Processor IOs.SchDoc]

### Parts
(Parts that share a designator on the sheet are numbered #1, #2 ... from top to bottom, then left to right.)
?#4  (no value)  (graphical)
R31  value 22R  Package: 0402  Tolerance: 1%  [RES_C_0402]  (hidden comment: Resistor)
R32  value 22R  Package: 0402  Tolerance: 1%  [RES_C_0402]  (hidden comment: Resistor)
R38  value 22R  Package: 0402  Tolerance: 1%  [RES_C_0402]  (hidden comment: Resistor)
R39  value 22R  Package: 0402  Tolerance: 1%  [RES_C_0402]  (hidden comment: Resistor)
R40  value 22R  Package: 0402  Tolerance: 1%  [RES_C_0402]  (hidden comment: Resistor)
R41  value 22R  Package: 0402  Tolerance: 1%  [RES_C_0402]  (hidden comment: Resistor)
R42  value 22R  Package: 0402  Tolerance: 1%  [RES_C_0402]  (hidden comment: Resistor)
R43  value 22R  Package: 0402  Tolerance: 1%  [RES_C_0402]  (hidden comment: Resistor)
R44  value 22R  Package: 0402  Tolerance: 1%  [RES_C_0402]  (hidden comment: Resistor)
R45  value 22R  Package: 0402  Tolerance: 1%  [RES_C_0402]  (hidden comment: Resistor)
R46  value 22R  Package: 0402  Tolerance: 1%  [RES_C_0402]  (hidden comment: Resistor)
R50  value 22R  Package: 0402  Tolerance: 1%  [RES_C_0402]  (hidden comment: Resistor)
R51  value 22R  Package: 0402  Tolerance: 1%  [RES_C_0402]  (hidden comment: Resistor)
R52  value 22R  Package: 0402  Tolerance: 1%  [RES_C_0402]  (hidden comment: Resistor)
R53  value 22R  Package: 0402  Tolerance: 1%  [RES_C_0402]  (hidden comment: Resistor)
R54  value 22R  Package: 0402  Tolerance: 1%  [RES_C_0402]  (hidden comment: Resistor)
R55  value 22R  Package: 0402  Tolerance: 1%  [RES_C_0402]  (hidden comment: Resistor)
R56  value 22R  Package: 0402  Tolerance: 1%  [RES_C_0402]  (hidden comment: Resistor)
R57  value 22R  Package: 0402  Tolerance: 1%  [RES_C_0402]  (hidden comment: Resistor)
R58  value 22R  Package: 0402  Tolerance: 1%  [RES_C_0402]  (hidden comment: Resistor)
R59  value 22R  Package: 0402  Tolerance: 1%  [RES_C_0402]  (hidden comment: Resistor)
R60  value 0R  Package: 0402  [RES_C_0402]  (hidden comment: Resistor)
R63  value 0R  Package: 0402  [RES_C_0402]  (hidden comment: Resistor)
R65  value 0R  Package: 0402  [RES_C_0402]  (hidden comment: Resistor)
R66  value 0R  Package: 0402  [RES_C_0402]  (hidden comment: Resistor)
R69  value 22R  Package: 0402  Tolerance: 1%  [RES_C_0402]  (hidden comment: Resistor)
R70  value 22R  Package: 0402  Tolerance: 1%  [RES_C_0402]  (hidden comment: Resistor)
R71  value 22R  Package: 0402  Tolerance: 1%  [RES_C_0402]  (hidden comment: Resistor)
R72  value 22R  Package: 0402  Tolerance: 1%  [RES_C_0402]  (hidden comment: Resistor)
R74  value 22R  Package: 0402  Tolerance: 1%  [RES_C_0402]  (hidden comment: Resistor)
R75  value 22R  Package: 0402  Tolerance: 1%  [RES_C_0402]  (hidden comment: Resistor)
R77  value 22R  Package: 0402  Tolerance: 1%  [RES_C_0402]  (hidden comment: Resistor)
R79  value 22R  Package: 0402  Tolerance: 1%  [RES_C_0402]  (hidden comment: Resistor)
R80  value 22R  Package: 0402  Tolerance: 1%  [RES_C_0402]  (hidden comment: Resistor)
R81  value 22R  Package: 0402  Tolerance: 1%  [RES_C_0402]  (hidden comment: Resistor)
R82  value 22R  Package: 0402  Tolerance: 1%  [RES_C_0402]  (hidden comment: Resistor)
R85  value 22R  Package: 0402  Tolerance: 1%  [RES_C_0402]  (hidden comment: Resistor)
R86  value 22R  Package: 0402  Tolerance: 1%  [RES_C_0402]  (hidden comment: Resistor)
R88  value 22R  Package: 0402  Tolerance: 1%  [RES_C_0402]  (hidden comment: Resistor)
U5  value SAM9X60-V/DWB  [SAM9X60 TFBGA-228]  (hidden comment: SAM9X60 TFBGA-228)  (parts A,B,C,D of 7)

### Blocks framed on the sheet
SAM9X60 PIOs: U5
SAM9X60 PIO Muxing: R31 R32 R38-R46 R50-R60 R63 R65 R66 R69-R72 R74 R75 R77 R79-R82 R85 R86 R88

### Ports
CAN/DBGU_RX_PA09 (in), CAN/DBGU_TX_PA10 (out), CAN/FLEXCOM_RX_PA06 (in), CAN/FLEXCOM_TX_PA05 (out), CAN_STBY_PD21 (out), CLASSD_L0_PA24 (out), CLASSD_L1_PA25 (out), CLASSD_L2_PA26 (out), CLASSD_L3_PA27 (out), ETH0_IRQ_PB08 (in), ETH0_MDC_PB06 (out), ETH0_MDIO_PB05 (out), ETH0_PCK1_PC31 (out), ETH0_RX0_PB00 (in), ETH0_RX1_PB01 (in), ETH0_RXDV_PB03 (in), ETH0_RXER_PB02 (in), ETH0_TX0_PB09 (out), ETH0_TX1_PB10 (out), ETH0_TXCK_PB04 (in), ETH0_TXEN_PB07 (out), EXT40_CLK1_PC31 (in), EXT40_CLK2_PB13 (out), EXT40_GPIO_PA02 (bidir), EXT40_GPIO_PA03 (bidir), EXT40_GPIO_PA04 (bidir), EXT40_GPIO_PA14 (bidir), EXT40_GPIO_PB24 (bidir), EXT40_I2SCK_PB19 (bidir), EXT40_I2SDIN_PB21 (in), EXT40_I2SDOUT_PB22 (out), EXT40_I2SMCK_PB23 (in), EXT40_I2SWS_PB20 (bidir), EXT40_NPCS1_PA07 (out), EXT40_NPCS2_PA08 (out), EXT40_PWM0_PB11 (out), EXT40_PWM1_PB12 (out), EXT40_SPI_MISO_PA11 (out), EXT40_SPI_MOSI_PA12 (in), EXT40_SPI_SCLK_PA13 (in), FLEXCOM0_IO0_PA00 (bidir), FLEXCOM0_IO1_PA01 (out), FLEXCOM5_IO0_TX_PA22 (out), FLEXCOM5_IO1_RX_PA21 (in), FLEXCOM5_IO3_BT_CTS_PA08 (out), FLEXCOM5_IO4_BT_RTS_PA07 (in), FLEXCOM6_TWCK_PA31 (out), FLEXCOM6_TWD_PA30 (bidir), LCD_D0_ISI_D0_PC00 (bidir), LCD_D1_ISI_D1_PC01 (bidir), LCD_D2_ISI_D2_PC02 (bidir), LCD_D3_ISI_D3_PC03 (bidir), LCD_D4_ISI_D4_PC04 (bidir), LCD_D5_ISI_D5_PC05 (bidir), LCD_D6_ISI_D6_PC06 (bidir), LCD_D7_ISI_D7_PC07 (bidir), LCD_D8_ISI_D8_PC08 (bidir), LCD_D9_ISI_D9_PC09 (bidir), LCD_D10_ISI_D10_PC10 (bidir), LCD_D11_ISI_D11_PC11 (bidir), LCD_D12_ISI_PCK_PC12 (bidir), LCD_D13_ISI_VSYNC_PC13 (bidir), LCD_D14_ISI_HSYNC_PC14 (bidir), LCD_D15_ISI_MCK_PC15 (bidir), LCD_D16_ISI_nRST_PC16 (bidir), LCD_D17_PC17 (out), LCD_D18_PC18 (out), LCD_D19_PC19 (out), LCD_D20_PC20 (out), LCD_D21_PC21 (out), LCD_D22_PC22 (out), LCD_D23_PC23 (out), LCD_DATA_ENABLE_PC29 (out), LCD_HSYNC/WE_PC28 (out), LCD_ID_PD14 (bidir), LCD_IRQ1_PC25 (out), LCD_IRQ2_PB17 (out), LCD_ISI_ENABLE_PC24 (out), LCD_PCLK_PC30 (out), LCD_PWM_PC26 (out), LCD_VSYNC/CS_PC27 (out), LED_BLUE_PB13 (out), LED_GREEN_PB12 (out), LED_RED_PB11 (out), MBUS_AD4_PB15 (in), MBUS_INT_PB18 (in), MBUS_MISO_PA11 (out), MBUS_MOSI_PA12 (in), MBUS_NPCS0_PA14 (out), MBUS_PWM_PB13 (out), MBUS_RST_PB14 (out), MBUS_SPCK_PA13 (in), MCP23008_INT_PD17 (in), NAND_ALE_PD02 (out), NAND_CLE_PD03 (out), NAND_IO0_PD06 (bidir), NAND_IO1_PD07 (bidir), NAND_IO2_PD08 (bidir), NAND_IO3_PD09 (bidir), NAND_IO4_PD10 (bidir), NAND_IO5_PD11 (bidir), NAND_IO6_PD12 (bidir), NAND_IO7_PD13 (bidir), NAND_nCS_PD04 (out), NAND_nRE_PD00 (out), NAND_nWE_PD01 (out), NAND_RB_PD05 (in), NRST_PB25 (out), QSPI_CS_PB20 (out), QSPI_IO0_PB21 (bidir), QSPI_IO1_PB22 (bidir), QSPI_IO2_PB23 (bidir), QSPI_IO3_PB24 (bidir), QSPI_SCK_PB19 (out), SDMMC0_CD_PA23 (in), SDMMC0_CLK_PA17 (out), SDMMC0_CMD_PA16 (in), SDMMC0_DAT0_PA15 (bidir), SDMMC0_DAT1_PA18 (bidir), SDMMC0_DAT2_PA19 (bidir), SDMMC0_DAT3_PA20 (bidir), SDMMC1_WILC3000_CK_PA13 (in), SDMMC1_WILC3000_CMD_PA12 (in), SDMMC1_WILC3000_DAT0_PA11 (bidir), SDMMC1_WILC3000_DAT1_PA02 (bidir), SDMMC1_WILC3000_DAT2_PA03 (bidir), SDMMC1_WILC3000_DAT3_PA04 (bidir), SEL_FNCT1_PD19 (out), SEL_FNCT2_PD20 (out), USBA_VBUSDETECT_PB16 (in), USBB_EN_5V_PD15 (out), USBC_EN_5V_PD16 (out), USER_BUTTON_PD18 (in), WILC3000_ENABLE_PA29 (out), WILC3000_INTERRUPT_PA28 (in)

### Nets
CAN/DBGU_RX_PA09: U5.G8(PA9) ; port CAN/DBGU_RX_PA09
CAN/DBGU_TX_PA10: U5.L2(PA10) ; port CAN/DBGU_TX_PA10
CAN/FLEXCOM_RX_PA06: U5.M2(PA6) ; port CAN/FLEXCOM_RX_PA06
CAN/FLEXCOM_TX_PA05: U5.L4(PA5) ; port CAN/FLEXCOM_TX_PA05
CAN_STBY_PD21: U5.M15(PD21) ; port CAN_STBY_PD21
CLASSD_L0_PA24: U5.F8(PA24) ; port CLASSD_L0_PA24
CLASSD_L1_PA25: U5.H1(PA25) ; port CLASSD_L1_PA25
CLASSD_L2_PA26: U5.F7(PA26) ; port CLASSD_L2_PA26
CLASSD_L3_PA27: U5.H2(PA27) ; port CLASSD_L3_PA27
ETH0_IRQ_PB08: U5.E6(PB8) ; port ETH0_IRQ_PB08
ETH0_MDC_PB06: U5.D2(PB6) ; port ETH0_MDC_PB06
ETH0_MDIO_PB05: U5.E1(PB5) ; port ETH0_MDIO_PB05
ETH0_PCK1_PC31: R88.1 ; port ETH0_PCK1_PC31
ETH0_RX0_PB00: U5.F4(PB0) ; port ETH0_RX0_PB00
ETH0_RX1_PB01: U5.C1(PB1) ; port ETH0_RX1_PB01
ETH0_RXDV_PB03: U5.D1(PB3) ; port ETH0_RXDV_PB03
ETH0_RXER_PB02: U5.D3(PB2) ; port ETH0_RXER_PB02
ETH0_TX0_PB09: U5.A2(PB9) ; port ETH0_TX0_PB09
ETH0_TX1_PB10: U5.A3(PB10) ; port ETH0_TX1_PB10
ETH0_TXCK_PB04: U5.E3(PB4) ; port ETH0_TXCK_PB04
ETH0_TXEN_PB07: U5.A5(PB7) ; port ETH0_TXEN_PB07
EXT40_CLK1_PC31: R86.1 ; port EXT40_CLK1_PC31
EXT40_CLK2_PB13: R66.2 ; port EXT40_CLK2_PB13
EXT40_GPIO_PA02: R32.1 ; port EXT40_GPIO_PA02
EXT40_GPIO_PA03: R39.1 ; port EXT40_GPIO_PA03
EXT40_GPIO_PA04: R41.1 ; port EXT40_GPIO_PA04
EXT40_GPIO_PA14: R59.1 ; port EXT40_GPIO_PA14
EXT40_GPIO_PB24: R82.1 ; port EXT40_GPIO_PB24
EXT40_I2SCK_PB19: R69.1 ; port EXT40_I2SCK_PB19
EXT40_I2SDIN_PB21: R74.1 ; port EXT40_I2SDIN_PB21
EXT40_I2SDOUT_PB22: R77.1 ; port EXT40_I2SDOUT_PB22
EXT40_I2SMCK_PB23: R80.1 ; port EXT40_I2SMCK_PB23
EXT40_I2SWS_PB20: R71.1 ; port EXT40_I2SWS_PB20
EXT40_NPCS1_PA07: R43.1 ; port EXT40_NPCS1_PA07
EXT40_NPCS2_PA08: R45.1 ; port EXT40_NPCS2_PA08
EXT40_PWM0_PB11: R60.2 ; port EXT40_PWM0_PB11
EXT40_PWM1_PB12: R63.2 ; port EXT40_PWM1_PB12
EXT40_SPI_MISO_PA11: R51.1 ; port EXT40_SPI_MISO_PA11
EXT40_SPI_MOSI_PA12: R54.1 ; port EXT40_SPI_MOSI_PA12
EXT40_SPI_SCLK_PA13: R57.1 ; port EXT40_SPI_SCLK_PA13
FLEXCOM0_IO0_PA00: U5.P2(PA0) ; port FLEXCOM0_IO0_PA00
FLEXCOM0_IO1_PA01: U5.M3(PA1) ; port FLEXCOM0_IO1_PA01
FLEXCOM5_IO0_TX_PA22: U5.G1(PA22) ; port FLEXCOM5_IO0_TX_PA22
FLEXCOM5_IO1_RX_PA21: U5.G6(PA21) ; port FLEXCOM5_IO1_RX_PA21
FLEXCOM5_IO3_BT_CTS_PA08: R44.1 ; port FLEXCOM5_IO3_BT_CTS_PA08
FLEXCOM5_IO4_BT_RTS_PA07: R42.1 ; port FLEXCOM5_IO4_BT_RTS_PA07
FLEXCOM6_TWCK_PA31: U5.H4(PA31) ; port FLEXCOM6_TWCK_PA31
FLEXCOM6_TWD_PA30: U5.G2(PA30) ; port FLEXCOM6_TWD_PA30
LCD_D0_ISI_D0_PC00: U5.M4(PC0) ; port LCD_D0_ISI_D0_PC00
LCD_D1_ISI_D1_PC01: U5.P4(PC1) ; port LCD_D1_ISI_D1_PC01
LCD_D2_ISI_D2_PC02: U5.N5(PC2) ; port LCD_D2_ISI_D2_PC02
LCD_D3_ISI_D3_PC03: U5.P5(PC3) ; port LCD_D3_ISI_D3_PC03
LCD_D4_ISI_D4_PC04: U5.L5(PC4) ; port LCD_D4_ISI_D4_PC04
LCD_D5_ISI_D5_PC05: U5.R4(PC5) ; port LCD_D5_ISI_D5_PC05
LCD_D6_ISI_D6_PC06: U5.M6(PC6) ; port LCD_D6_ISI_D6_PC06
LCD_D7_ISI_D7_PC07: U5.T3(PC7) ; port LCD_D7_ISI_D7_PC07
LCD_D8_ISI_D8_PC08: U5.N8(PC8) ; port LCD_D8_ISI_D8_PC08
LCD_D9_ISI_D9_PC09: U5.T4(PC9) ; port LCD_D9_ISI_D9_PC09
LCD_D10_ISI_D10_PC10: U5.P6(PC10) ; port LCD_D10_ISI_D10_PC10
LCD_D11_ISI_D11_PC11: U5.N6(PC11) ; port LCD_D11_ISI_D11_PC11
LCD_D12_ISI_PCK_PC12: U5.R5(PC12) ; port LCD_D12_ISI_PCK_PC12
LCD_D13_ISI_VSYNC_PC13: U5.L7(PC13) ; port LCD_D13_ISI_VSYNC_PC13
LCD_D14_ISI_HSYNC_PC14: U5.T5(PC14) ; port LCD_D14_ISI_HSYNC_PC14
LCD_D15_ISI_MCK_PC15: U5.J7(PC15) ; port LCD_D15_ISI_MCK_PC15
LCD_D16_ISI_nRST_PC16: U5.R6(PC16) ; port LCD_D16_ISI_nRST_PC16
LCD_D17_PC17: U5.K8(PC17) ; port LCD_D17_PC17
LCD_D18_PC18: U5.T6(PC18) ; port LCD_D18_PC18
LCD_D19_PC19: U5.L8(PC19) ; port LCD_D19_PC19
LCD_D20_PC20: U5.P8(PC20) ; port LCD_D20_PC20
LCD_D21_PC21: U5.M8(PC21) ; port LCD_D21_PC21
LCD_D22_PC22: U5.R7(PC22) ; port LCD_D22_PC22
LCD_D23_PC23: U5.K9(PC23) ; port LCD_D23_PC23
LCD_DATA_ENABLE_PC29: U5.L10(PC29) ; port LCD_DATA_ENABLE_PC29
LCD_HSYNC/WE_PC28: U5.N9(PC28) ; port LCD_HSYNC/WE_PC28
LCD_ID_PD14: U5.L12(PD14) ; port LCD_ID_PD14
LCD_IRQ1_PC25: U5.L9(PC25) ; port LCD_IRQ1_PC25
LCD_IRQ2_PB17: U5.B1(PB17) ; port LCD_IRQ2_PB17
LCD_ISI_ENABLE_PC24: U5.R8(PC24) ; port LCD_ISI_ENABLE_PC24
LCD_PCLK_PC30: U5.T7(PC30) ; port LCD_PCLK_PC30
LCD_PWM_PC26: U5.T8(PC26) ; port LCD_PWM_PC26
LCD_VSYNC/CS_PC27: U5.M9(PC27) ; port LCD_VSYNC/CS_PC27
MBUS_AD4_PB15: U5.B5(PB15) ; port MBUS_AD4_PB15
MBUS_INT_PB18: U5.E4(PB18) ; port MBUS_INT_PB18
MBUS_MISO_PA11: R50.1 ; port MBUS_MISO_PA11
MBUS_MOSI_PA12: R53.1 ; port MBUS_MOSI_PA12
MBUS_NPCS0_PA14: R58.1 ; port MBUS_NPCS0_PA14
MBUS_PWM_PB13: R65.2 ; port MBUS_PWM_PB13
MBUS_RST_PB14: U5.F2(PB14) ; port MBUS_RST_PB14
MBUS_SPCK_PA13: R56.1 ; port MBUS_SPCK_PA13
MCP23008_INT_PD17: U5.N16(PD17) ; port MCP23008_INT_PD17
NAND_ALE_PD02: U5.P15(PD2) ; port NAND_ALE_PD02
NAND_CLE_PD03: U5.N14(PD3) ; port NAND_CLE_PD03
NAND_IO0_PD06: U5.K16(PD6) ; port NAND_IO0_PD06
NAND_IO1_PD07: U5.J12(PD7) ; port NAND_IO1_PD07
NAND_IO2_PD08: U5.K15(PD8) ; port NAND_IO2_PD08
NAND_IO3_PD09: U5.J10(PD9) ; port NAND_IO3_PD09
NAND_IO4_PD10: U5.L16(PD10) ; port NAND_IO4_PD10
NAND_IO5_PD11: U5.K11(PD11) ; port NAND_IO5_PD11
NAND_IO6_PD12: U5.L15(PD12) ; port NAND_IO6_PD12
NAND_IO7_PD13: U5.J15(PD13) ; port NAND_IO7_PD13
NAND_nCS_PD04: U5.R16(PD4) ; port NAND_nCS_PD04
NAND_nRE_PD00: U5.R14(PD0) ; port NAND_nRE_PD00
NAND_nWE_PD01: U5.T15(PD1) ; port NAND_nWE_PD01
NAND_RB_PD05: U5.N11(PD5) ; port NAND_RB_PD05
NRST_PB25: U5.E2(PB25) ; port NRST_PB25
PA02: R31.2 R32.2 U5.P1(PA2)
PA03: R38.2 R39.2 U5.L3(PA3)
PA04: R40.2 R41.2 U5.N1(PA4)
PA07: R42.2 R43.2 U5.K6(PA7)
PA08: R44.2 R45.2 U5.M1(PA8)
PA11: R46.2 R50.2 R51.2 U5.H7(PA11)
PA12: R52.2 R53.2 R54.2 U5.L1(PA12)
PA13: R55.2 R56.2 R57.2 U5.J6(PA13)
PA14: R58.2 R59.2 U5.K1(PA14)
PB11: R60.1 U5.D6(PB11) ; port LED_RED_PB11
PB12: R63.1 U5.C2(PB12) ; port LED_GREEN_PB12
PB13: R65.1 R66.1 U5.A4(PB13) ; port LED_BLUE_PB13
PB19: R69.2 R70.2 U5.C6(PB19)
PB20: R71.2 R72.2 U5.A6(PB20)
PB21: R74.2 R75.2 U5.A7(PB21)
PB22: R77.2 R79.2 U5.B7(PB22)
PB23: R80.2 R81.2 U5.B6(PB23)
PB24: R82.2 R85.2 U5.A8(PB24)
PC31: R86.2 R88.2 U5.M13(PC31)
QSPI_CS_PB20: R72.1 ; port QSPI_CS_PB20
QSPI_IO0_PB21: R75.1 ; port QSPI_IO0_PB21
QSPI_IO1_PB22: R79.1 ; port QSPI_IO1_PB22
QSPI_IO2_PB23: R81.1 ; port QSPI_IO2_PB23
QSPI_IO3_PB24: R85.1 ; port QSPI_IO3_PB24
QSPI_SCK_PB19: R70.1 ; port QSPI_SCK_PB19
SDMMC0_CD_PA23: U5.J4(PA23) ; port SDMMC0_CD_PA23
SDMMC0_CLK_PA17: U5.J3(PA17) ; port SDMMC0_CLK_PA17
SDMMC0_CMD_PA16: U5.K2(PA16) ; port SDMMC0_CMD_PA16
SDMMC0_DAT0_PA15: U5.H6(PA15) ; port SDMMC0_DAT0_PA15
SDMMC0_DAT1_PA18: U5.J1(PA18) ; port SDMMC0_DAT1_PA18
SDMMC0_DAT2_PA19: U5.J5(PA19) ; port SDMMC0_DAT2_PA19
SDMMC0_DAT3_PA20: U5.J2(PA20) ; port SDMMC0_DAT3_PA20
SDMMC1_WILC3000_CK_PA13: R55.1 ; port SDMMC1_WILC3000_CK_PA13
SDMMC1_WILC3000_CMD_PA12: R52.1 ; port SDMMC1_WILC3000_CMD_PA12
SDMMC1_WILC3000_DAT0_PA11: R46.1 ; port SDMMC1_WILC3000_DAT0_PA11
SDMMC1_WILC3000_DAT1_PA02: R31.1 ; port SDMMC1_WILC3000_DAT1_PA02
SDMMC1_WILC3000_DAT2_PA03: R38.1 ; port SDMMC1_WILC3000_DAT2_PA03
SDMMC1_WILC3000_DAT3_PA04: R40.1 ; port SDMMC1_WILC3000_DAT3_PA04
SEL_FNCT1_PD19: U5.P16(PD19) ; port SEL_FNCT1_PD19
SEL_FNCT2_PD20: U5.M11(PD20) ; port SEL_FNCT2_PD20
USBA_VBUSDETECT_PB16: U5.B3(PB16) ; port USBA_VBUSDETECT_PB16
USBB_EN_5V_PD15: U5.M16(PD15) ; port USBB_EN_5V_PD15
USBC_EN_5V_PD16: U5.M14(PD16) ; port USBC_EN_5V_PD16
USER_BUTTON_PD18: U5.L13(PD18) ; port USER_BUTTON_PD18
WILC3000_ENABLE_PA29: U5.H3(PA29) ; port WILC3000_ENABLE_PA29
WILC3000_INTERRUPT_PA28: U5.F1(PA28) ; port WILC3000_INTERRUPT_PA28

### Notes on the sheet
- (near U5) SAM9X60 PORT PA
- (near U5) SAM9X60 PORT PC
- (near U5) SAM9X60 PORT PB
- (near U5) SAM9X60 PORT PD

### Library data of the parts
?#4 = Title Block B
R31 R32 R38-R46 R50-R59 R69-R72 R74 R75 R77 R79-R82 R85 R86 R88 = RES1474: Manufacturer 1: Panasonic Electronic Components; Manufacturer Part Number 1: ERJ-2RKF22R0X; Description_: RES TKF 22R 1% 1/20W SMD 0402; Dev Tools Status: Production; Temperature Coeffcient: 100ppm/C; Circuit Type: Isolated; Power: 1/10W; Owner: Mike Ragsdale; Populated: YES
R60 R63 R65 R66 = RSMT1040: as R26 on sheet 03 - Processor SAM9X60
U5 = MIC8772: as U5 on sheet 03 - Processor SAM9X60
